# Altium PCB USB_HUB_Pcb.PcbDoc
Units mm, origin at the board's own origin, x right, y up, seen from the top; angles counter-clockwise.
Board outline 72.5 x 95.02 mm, 4 copper layers (Top Layer, Int1 (GND), Int2 (PWR), Bottom Layer), stack 1.626 mm thick; 61 components, 56 nets, 230 pads, 681 vias.
Unrouted connection lines stored in the file: 103.
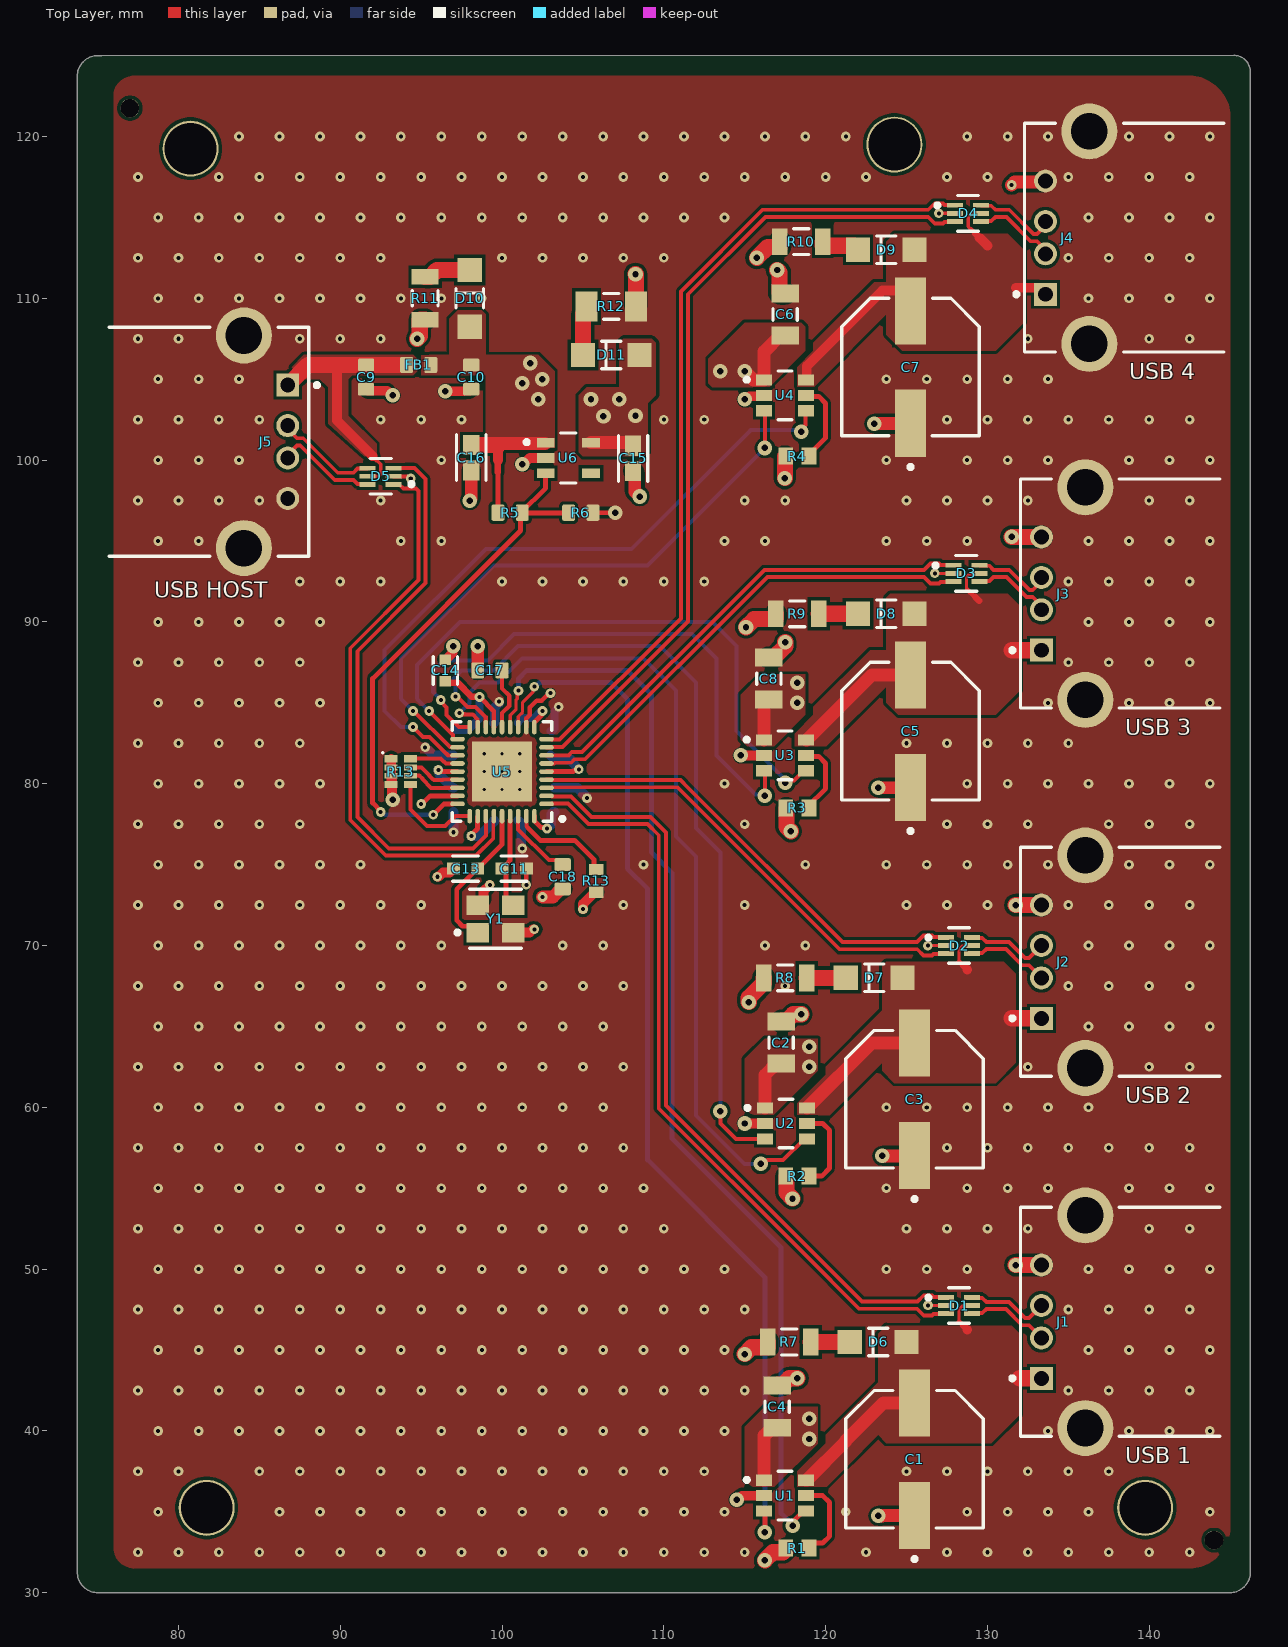
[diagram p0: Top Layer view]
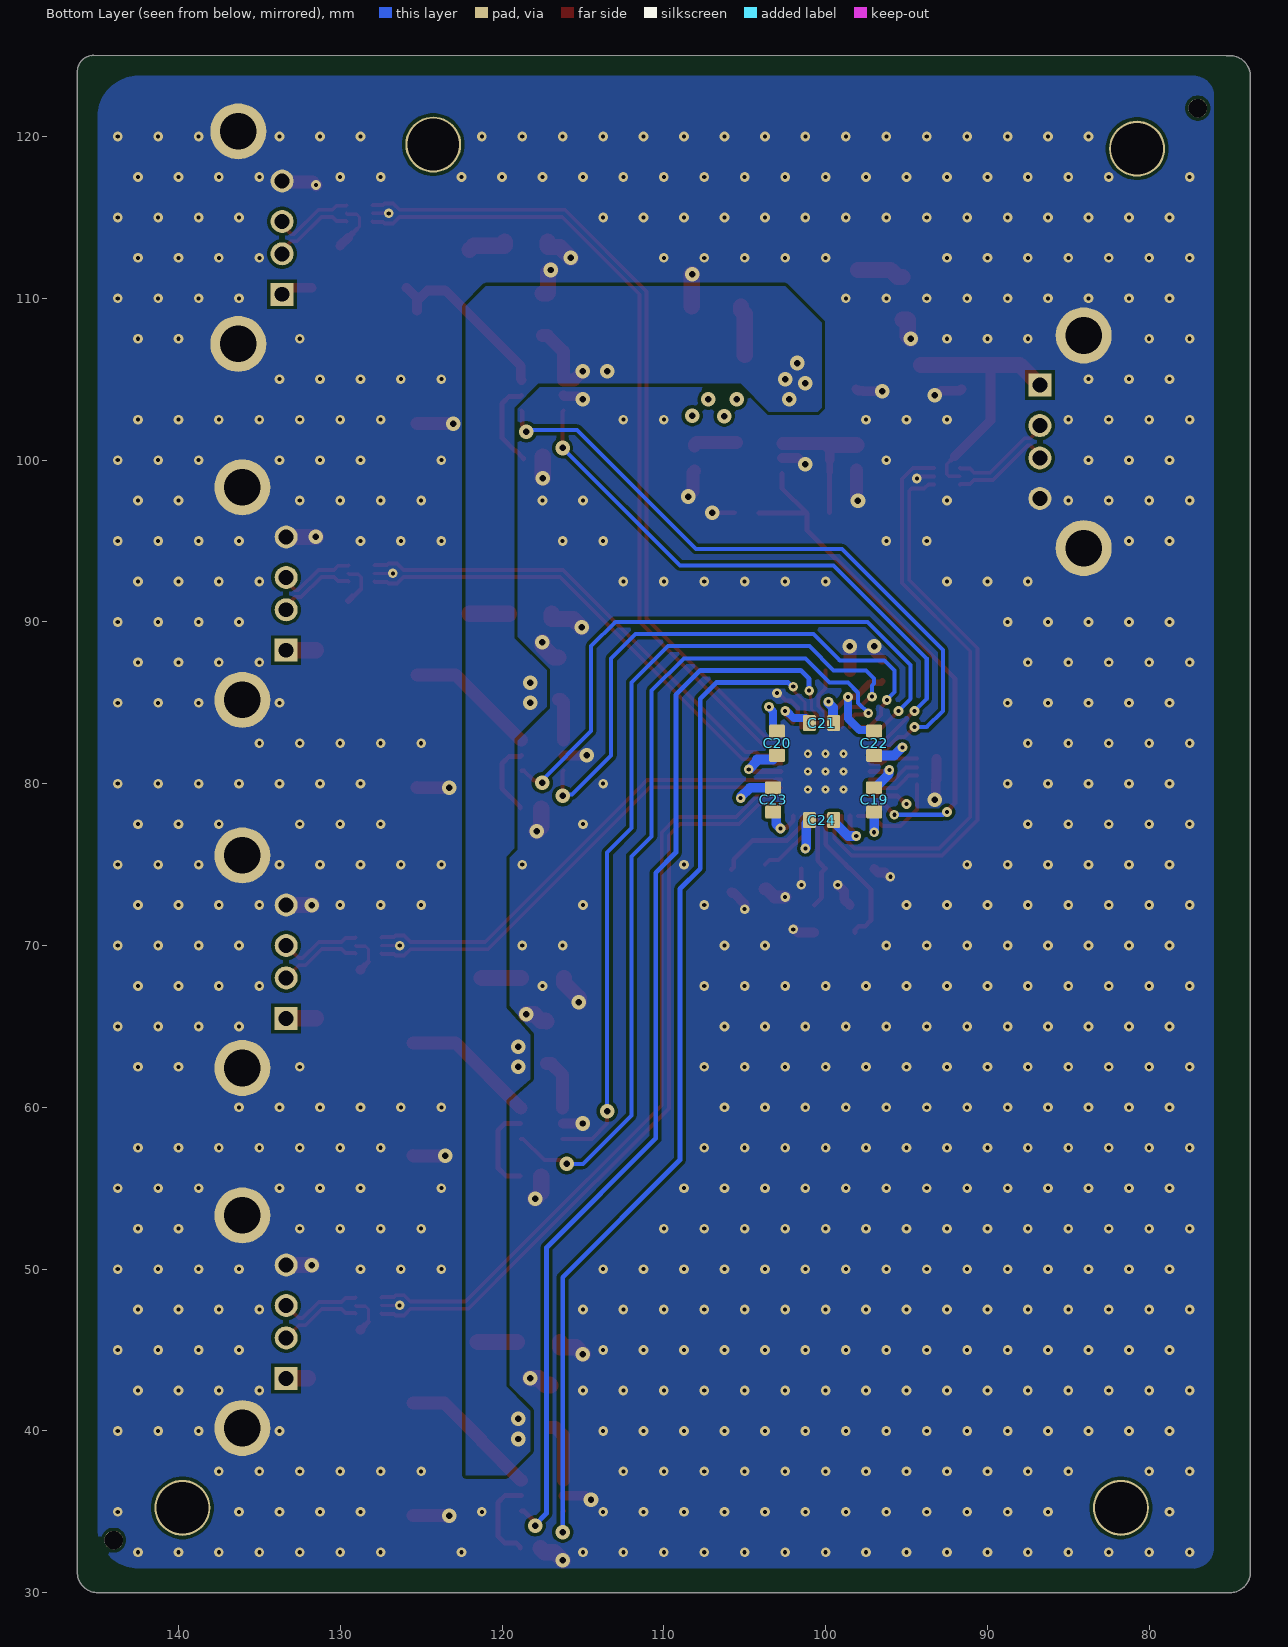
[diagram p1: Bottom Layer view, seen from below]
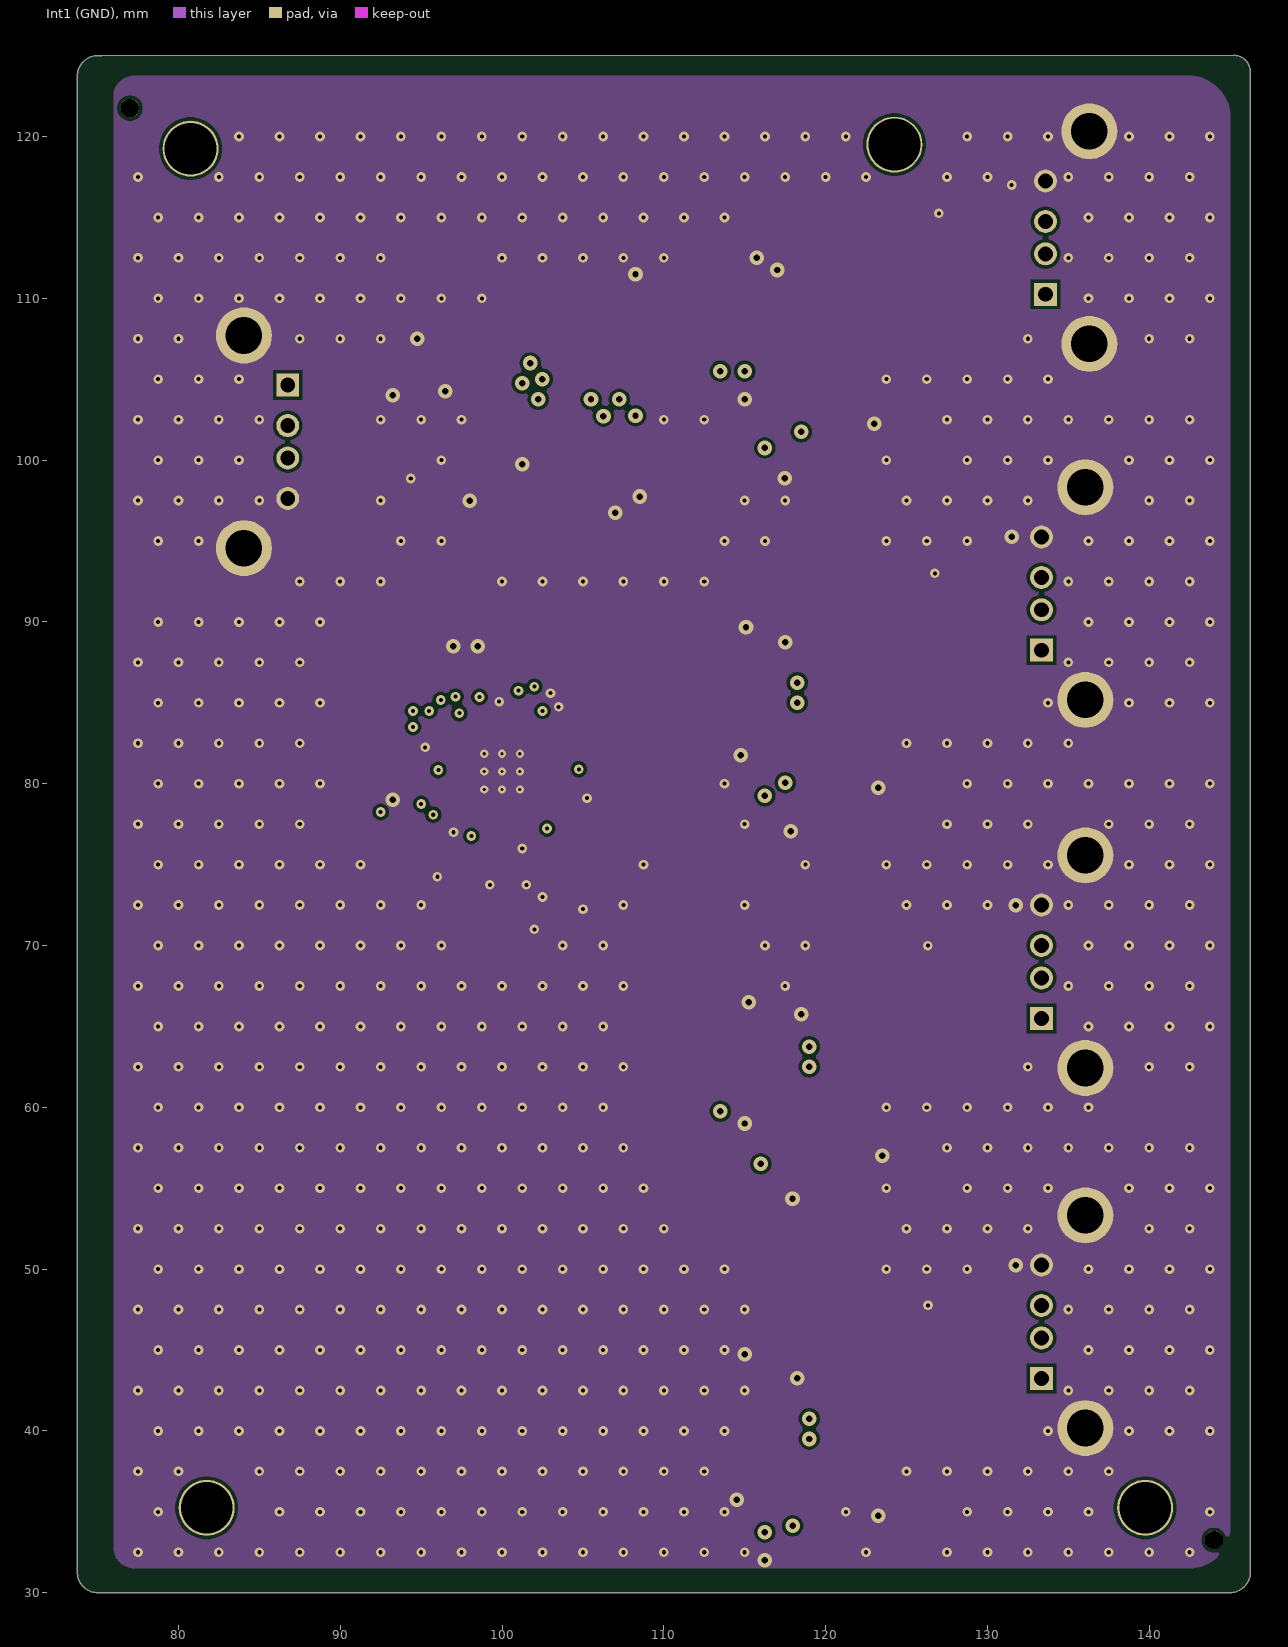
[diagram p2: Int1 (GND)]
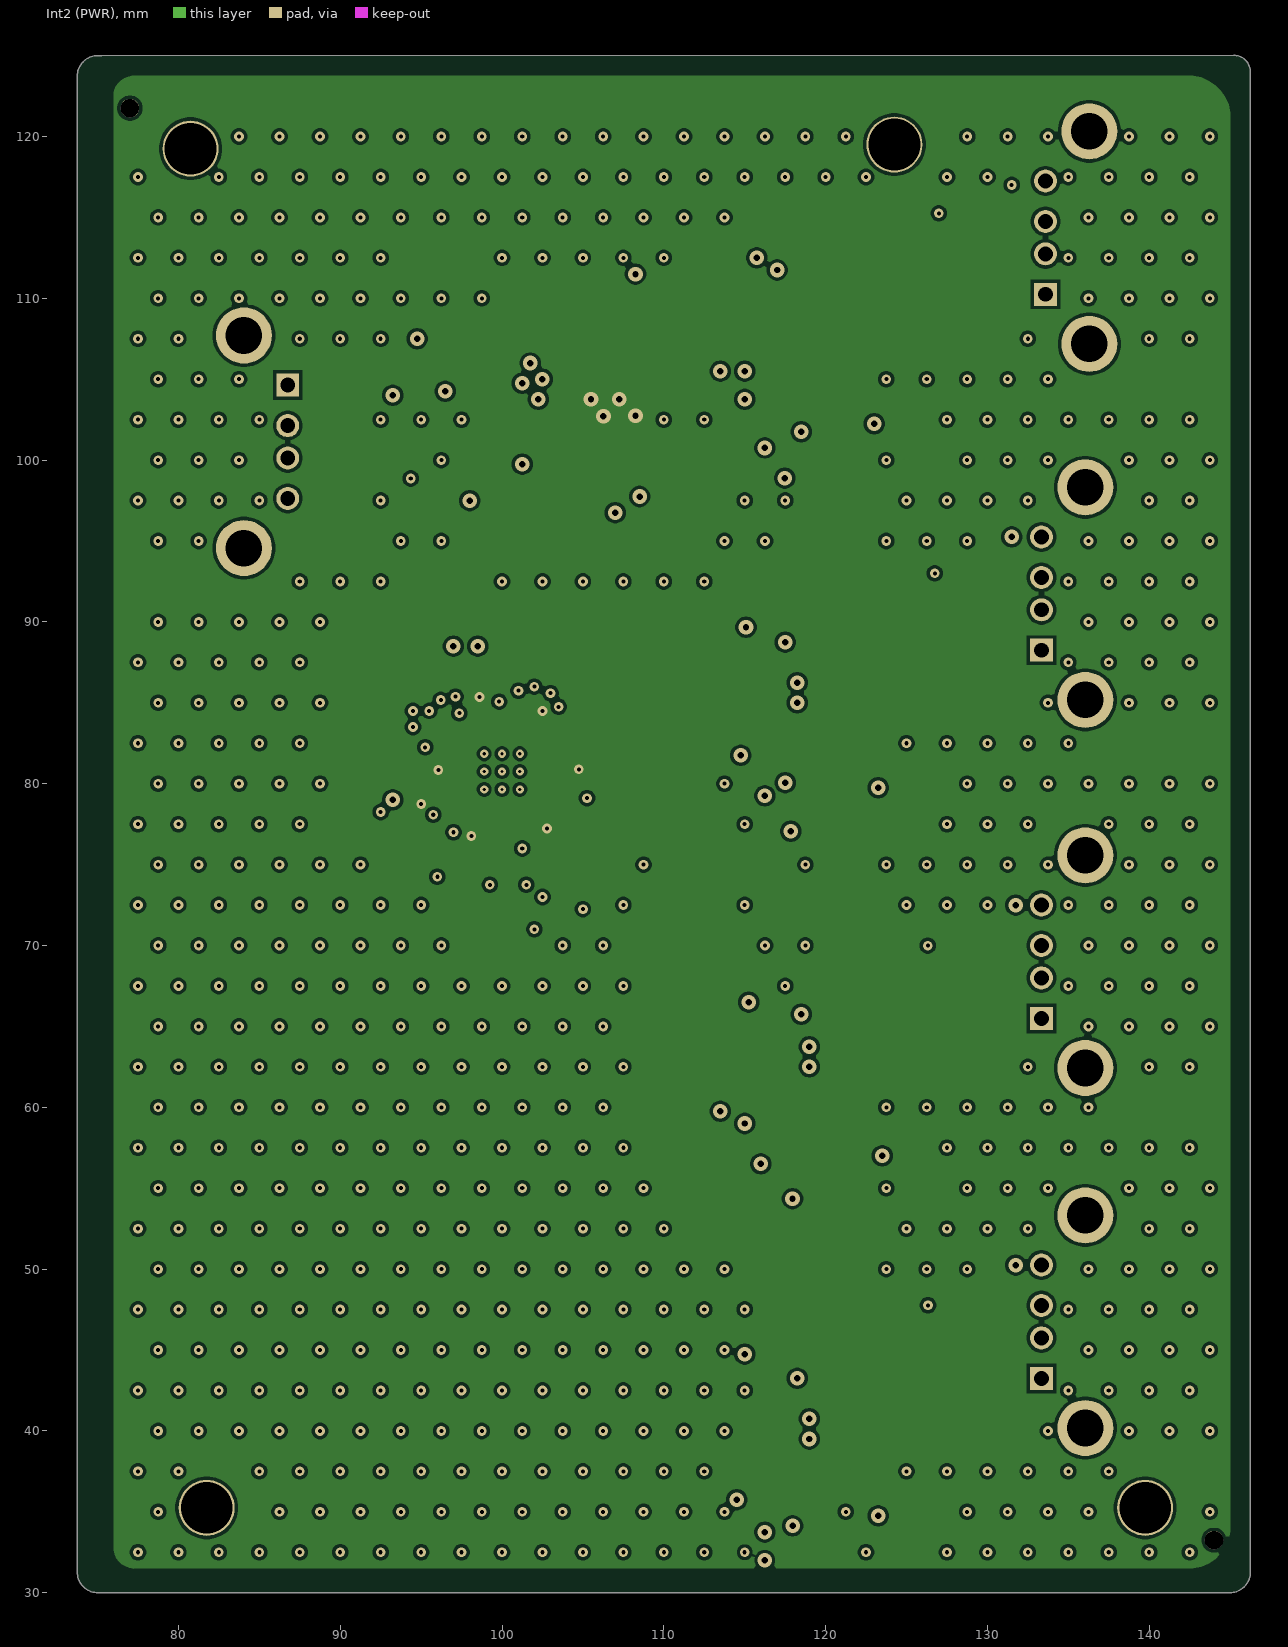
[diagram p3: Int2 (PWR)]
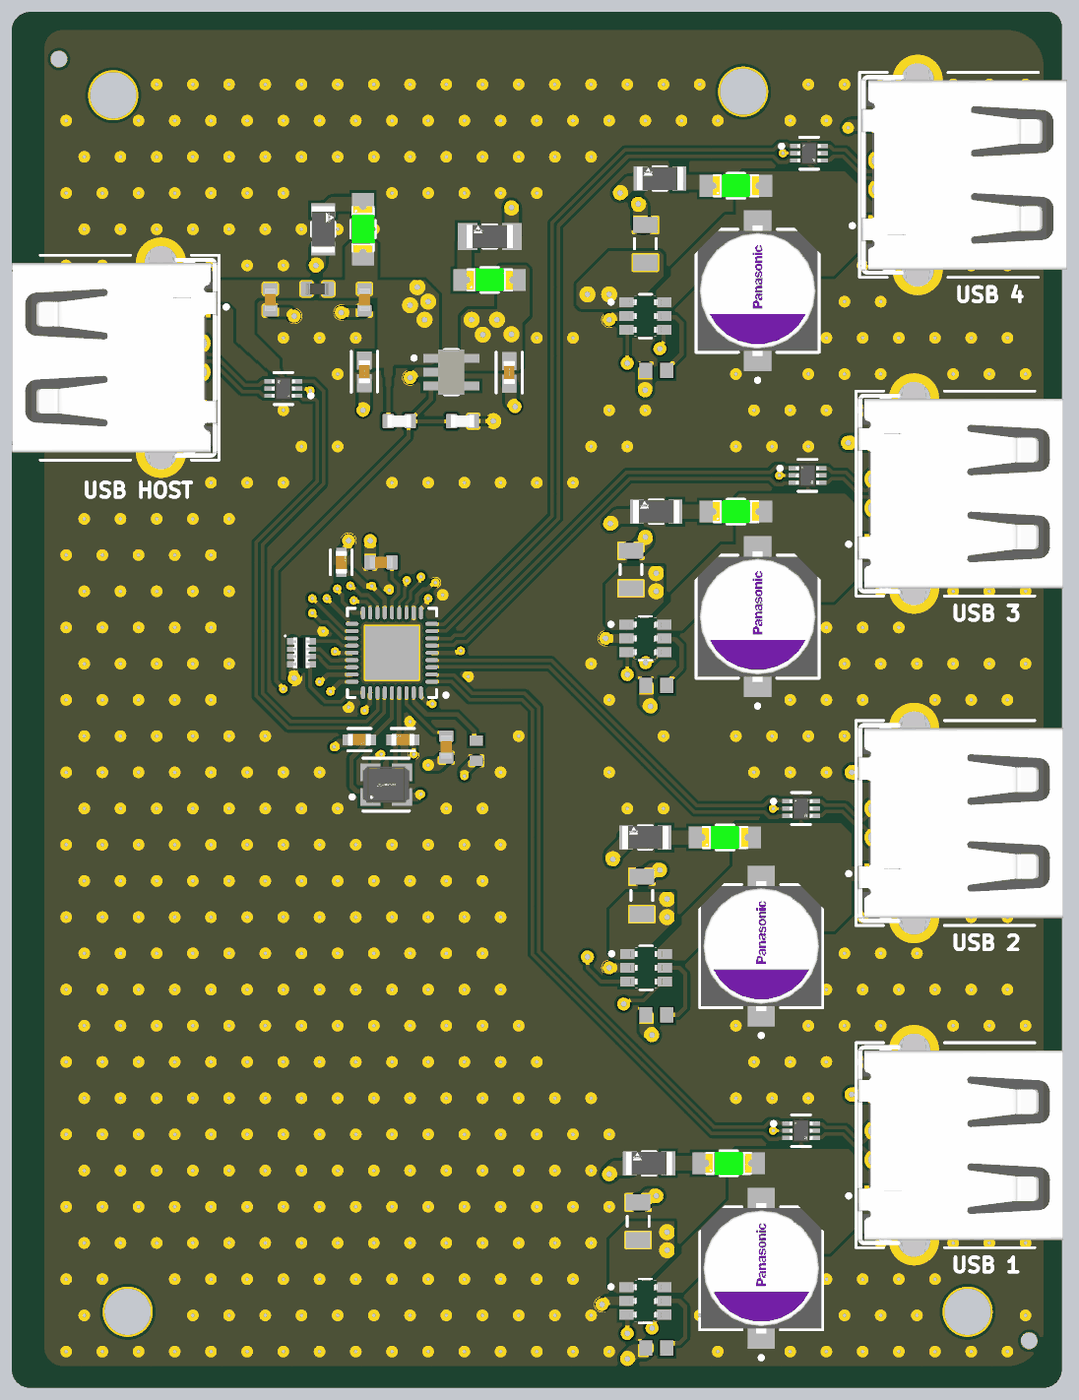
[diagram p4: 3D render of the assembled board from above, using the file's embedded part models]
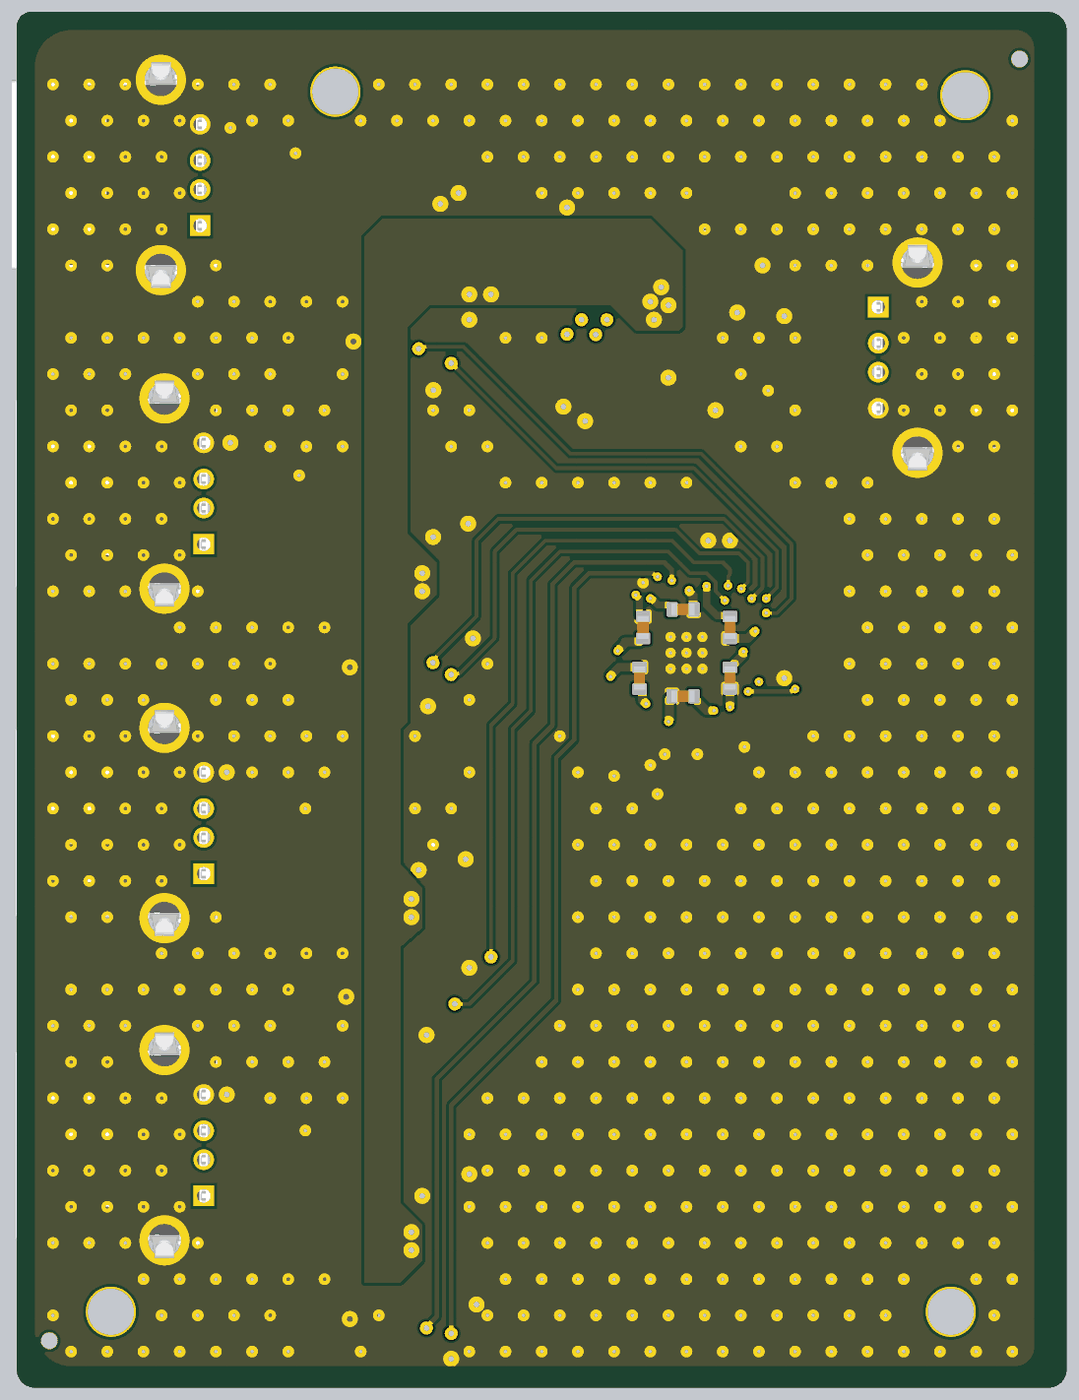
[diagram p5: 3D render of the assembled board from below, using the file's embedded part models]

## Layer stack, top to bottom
Top Solder: solder mask 0.0254, SM-001, Dk 4
Top Layer: signal copper 0.035
Dielectric 1: prepreg 0.2104, PP-017, Dk 4.74
Int1 (GND): signal copper 0.035
Dielectric 3: core 1.065, Core-039, Dk 4.6
Int2 (PWR): signal copper 0.035
Dielectric 2: prepreg 0.2104, PP-017, Dk 4.74
Bottom Layer: signal copper 0.035
Bottom Solder: solder mask 0.0254, SM-001, Dk 4

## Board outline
73.75,31.27 73.75,123.731 cw(c75.02,123.731) 75.02,125.001 75.25,125.001 145.25,125.02 145.23,125.02 cw(c145.23,124) 146.25,124 146.25,32.095 146.25,31.27 cw(c144.98,31.27) 144.98,30 144.75,30 75.5,30 75.02,30 cw(c75.02,31.27)

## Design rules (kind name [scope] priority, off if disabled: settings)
Clearance Clearance_1 [All] p1: gap=0.2 ignorepadtopadclearanceinfootprint=FALSE except(0: Hole-Hole; 0.15: SMDPad-SMDPad)
Clearance Clearance_1 [(ExistsOnLayer('Int1 (GND)') Or ExistsOnLayer('Int2 (PWR)')) vs (ExistsOnLayer('Int1 (GND)') Or ExistsOnLayer('Int2 (PWR)'))] p2: gap=0.2 ignorepadtopadclearanceinfootprint=FALSE except(0.254: Hole-Hole) sourcerule=44 cellrowname=All cellrowtype=0 cellcolname=All cellcoltype=0 innerlayers=TRUE
Clearance Clearance_2 [(ExistsOnLayer('Top Layer') Or ExistsOnLayer('Bottom Layer')) vs (ExistsOnLayer('Top Layer') Or ExistsOnLayer('Bottom Layer'))] p3: gap=0.2 ignorepadtopadclearanceinfootprint=FALSE except(0.254: Hole-Hole) sourcerule=44 cellrowname=All cellrowtype=0 cellcolname=All cellcoltype=0 outerlayers=TRUE
Clearance [All] p4: gap=0.254 ignorepadtopadclearanceinfootprint=FALSE ismatrix=TRUE
DiffPairsRouting DifferentialPairsRouting_1 [InDifferentialPairClass('All Differential Pairs')] p1: maxlimit=0.254 minlimit=0.2 mostfreqgap=0.254 toplayer_maxgap=0.2 toplayer_prefgap=0.2 toplayer_minwidth=0.242 toplayer_maxwidth=0.242 toplayer_prefwidth=0.242 bottomlayer_maxgap=0.2 bottomlayer_prefgap=0.2 bottomlayer_minwidth=0.242 bottomlayer_maxwidth=0.242 bottomlayer_prefwidth=0.242 impedanceprofiledriven=TRUE impedanceprofileid={922D21AE-9045-4F8F-8411-C6D0F4A54CC1} impedanceprofilevalue=90.000000 maxuncoupledlength=12.7
DiffPairsRouting [All] p2: maxlimit=0.254 minlimit=0.254 mostfreqgap=0.254 toplayer_minwidth=0.381 toplayer_maxwidth=0.381 toplayer_prefwidth=0.381 midlayer1_minwidth=0.381 midlayer1_maxwidth=0.381 midlayer1_prefwidth=0.381 midlayer2_minwidth=0.381 midlayer2_maxwidth=0.381 midlayer2_prefwidth=0.381 bottomlayer_minwidth=0.381 bottomlayer_maxwidth=0.381 bottomlayer_prefwidth=0.381 maxuncoupledlength=12.7
HoleSize MaxMinHoleSize_1 [All] p1: absolutevalues=TRUE maxlimit=6.2 minlimit=0.15 maxpercent=80.000 minpercent=20.000
HoleSize [All] p2: absolutevalues=TRUE maxlimit=2.54 minlimit=0.025 maxpercent=80.000 minpercent=20.000
HoleToHoleClearance [All] p1: gap=0.2 allowstackedmicrovias=TRUE
MinimumSolderMaskSliver [All] p1: minsoldermaskwidth=0.1
PlaneConnect [All] p1: planeconnectstyle=Direct reliefexpansion=0.508 reliefentries=4 reliefconductorwidth=0.254 reliefairgap=0.254
PolygonConnect [All] p1: connectstyle=Direct reliefconductorwidth=0.254 reliefentries=4 polygonreliefangle="90 Angle" airgapwidth=0.254
RoutingVias RoutingViaStyle_1 [All] p1: holewidth=0.3 width=0.7 viastyle="Through Hole" minholewidth=0.25 minwidth=0.55 maxholewidth=0.4 maxwidth=0.9
SolderMaskExpansion [All] p1: expansion=0.102 istentingtop=FALSE
SupplyNets "Schematic Supply Nets_3" [InNet('3V3')] p1: voltage=0.000
SupplyNets "Schematic Supply Nets_2" [InNet('GND')] p2: voltage=0.000
SupplyNets "Schematic Supply Nets_1" [InNet('VBUS')] p3: voltage=0.000
SupplyNets "Schematic Supply Nets" [InNet('VBUS_Filt')] p4: voltage=0.000
UnRoutedNet [All] p1: checkbadconnections=TRUE
Width MaxMinWidth_1 [All] p1: maxlimit=1 minlimit=0.2 preferedwidth=0.3 minimp=50.000000 maximp=50.000000 favimp=50.000000
Width MaxMinWidth_2 [All] p2: maxlimit=1 minlimit=0.2 preferedwidth=0.3 minimp=50.000000 maximp=50.000000 favimp=50.000000
24 further rules are at their usual default settings.

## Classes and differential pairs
differential pair "D_USB1 1 D": +"USB1 1 D_P" -"USB1 1 D_N"
differential pair "D_USB1 2 D": +"USB1 2 D_P" -"USB1 2 D_N"
differential pair "D_USB1 3 D": +"USB1 3 D_P" -"USB1 3 D_N"
differential pair "D_USB1 4 D": +"USB1 4 D_P" -"USB1 4 D_N"
differential pair "D_USB HOST1 D": +"USB HOST1 D_P" -"USB HOST1 D_N"
differential pair "D_USB 1 D": +"USB 1 D_P" -"USB 1 D_N"
differential pair "D_USB 2 D": +"USB 2 D_P" -"USB 2 D_N"
differential pair "D_USB 3 D": +"USB 3 D_P" -"USB 3 D_N"
differential pair "D_USB 4 D": +"USB 4 D_P" -"USB 4 D_N"
differential pair "D_USB HOST D": +"USB HOST D_P" -"USB HOST D_N"

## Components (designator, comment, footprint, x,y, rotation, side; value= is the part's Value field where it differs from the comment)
C1 "120u" FP-OS-CON-SMT-E7-MFG 125.5,38.25 r90 top
C2 "1u" CAPC3216X110X50LL20T25 117.25,64 r270 top
C3 "120u" FP-OS-CON-SMT-E7-MFG 125.5,60.5 r90 top
C4 "1u" CAPC3216X110X50LL20T25 117,41.5 r270 top
C5 "120u" FP-OS-CON-SMT-E7-MFG 125.25,83.25 r90 top
C6 "1u" CAPC3216X110X50LL20T25 117.5,109 r270 top
C7 "120u" FP-OS-CON-SMT-E7-MFG 125.25,105.75 r90 top
C8 "1u" CAPC3216X110X50LL20T25 116.5,86.5 r270 top
C9 "2u2" CAP_0603 91.599,105.132 r90 top
C10 "2u2" CAP_0603 98.099,105.132 r90 top
C11 "10p" FP-0603-L_1_6_0_15-W_0_81-MFG 100.75,74.75 r180 top
C13 "10p" FP-0603-L_1_6_0_15-W_0_81-MFG 97.75,74.75 r0 top
C14 "2u2" FP-GRM188-0_1-e0_2_0_5-MFG 96.5,87 r90 top
C15 "1u" FP-0603-L_1_6_0_1-W_0_8_0-IPC_A 108.099,100.105 r270 top
C16 "1u" FP-0603-L_1_6_0_1-W_0_8_0-IPC_A 98.099,100.159 r270 top
C17 "100nF" CAP_0603 99.25,87 r0 top
C18 "100nF" CAP_0603 103.75,74.25 r90 top
C19 "100n" CAP_0603 97,79 r90 bottom
C20 "100n" CAP_0603 103,82.5 r270 bottom
C21 "100n" CAP_0603 100.25,83.75 r0 bottom
C22 "100n" CAP_0603 97,82.5 r90 bottom
C23 "100n" CAP_0603 103.25,79 r270 bottom
C24 "100n" CAP_0603 100.25,77.75 r180 bottom
D1 "USBLC6-2P6" FP-SOT-666-MFG 128.25,47.75 r0 top
D2 "USBLC6-2P6" FP-SOT-666-MFG 128.25,70 r0 top
D3 "USBLC6-2P6" FP-SOT-666-MFG 128.695,93 r0 top
D4 "USBLC6-2P6" FP-SOT-666-MFG 128.805,115.25 r0 top
D5 "USBLC6-2P6" FP-SOT-666-MFG 92.5,99 r180 top
D6 "LED_GREEN" FP-HSMG-C150-MFG 123.25,45.5 r0 top
D7 "LED_GREEN" FP-HSMG-C150-MFG 123,68 r0 top
D8 "LED_GREEN" FP-HSMG-C150-MFG 123.75,90.5 r0 top
D9 "LED_GREEN" FP-HSMG-C150-MFG 123.75,113 r0 top
D10 "GREEN_LED" FP-HSMG-C150-MFG 98,110 r270 top
D11 "LED_GREEN" FP-HSMG-C150-MFG 106.75,106.5 r0 top
FB1 "120R" FB_0603 94.849,105.882 r0 top
J1 "USB1130-15-A" FP-USB1130-15-A-MFG 139.25,46.75 r90 top
J2 "USB1130-15-A" FP-USB1130-15-A-MFG 139.25,69 r90 top
J3 "USB1130-15-A" FP-USB1130-15-A-MFG 139.25,91.75 r90 top
J4 "USB1130-15-A" FP-USB1130-15-A-MFG 139.5,113.75 r90 top
J5 "USB1130-15-A" FP-USB1130-15-A-MFG 80.849,101.132 r270 top
R1 "470" RESC1608X55X30ML15T15 118.25,32.75 r0 top
R2 "470" RESC1608X55X30ML15T15 118.25,55.75 r0 top
R3 "470" RESC1608X55X30ML15T15 118.25,78.5 r0 top
R4 "470" RESC1608X55X30ML15T15 118.25,100.25 r0 top
R5 "100k" RES_0603 100.5,96.75 r180 top
R6 "100k" RES_0603 104.868,96.749 r180 top
R7 "180" FP-CRCW1206-e3-IPC_C 117.75,45.5 r180 top
R8 "180" FP-CRCW1206-e3-IPC_C 117.5,68 r180 top
R9 "180" FP-CRCW1206-e3-IPC_C 118.25,90.5 r180 top
R10 "180" FP-CRCW1206-e3-IPC_C 118.5,113.5 r180 top
R11 "180" FP-CRCW1206-e3-IPC_C 95.25,110 r90 top
R12 "82" FP-CRCW1206-e3-IPC_A 106.75,109.5 r180 top
R13 "4 resistor array" 0804 93.75,80.75 r0 top
R13 "12k" RESC1608X55X25NL10T15 105.821,73.999 r270 top
U1 "MIC2019YM6-TR" FP-SOT23-6LD-PL-1-MFG 117.5,36 r0 top
U2 "MIC2019YM6-TR" FP-SOT23-6LD-PL-1-MFG 117.545,59 r0 top
U3 "MIC2019YM6-TR" FP-SOT23-6LD-PL-1-MFG 117.5,81.75 r0 top
U4 "MIC2019YM6-TR" FP-SOT23-6LD-PL-1-MFG 117.5,104 r0 top
U5 "USB2514B-AEZC" MCHP-QFN-36_V 100,80.75 r180 top locked
U6 "MCP1755T-3302E/OT" FP-C04-091-OT-MFG 104.099,100.132 r0 top
Y1 "ABM8G-24.000MHZ-18-D2Y-T" FP-ABM8G-MFG 99.6,71.65 r0 top

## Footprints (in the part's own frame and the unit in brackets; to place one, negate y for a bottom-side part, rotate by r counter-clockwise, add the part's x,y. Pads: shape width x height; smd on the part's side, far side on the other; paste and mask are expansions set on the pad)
0804 [mm] "Chip Array, ConvexS, 8-Leads, Pitch 0.50mm,  Body 2.00x1.00mm,  IPC Medium Density"
  rect 0.8x0.45 smd mask+0: 2(0.6,0.8) 3(-0.6,0.8) 7(-0.6,-0.8) 8(0.6,-0.8)
  rect 0.8x0.35 smd mask+0: 3(-0.6,0.25) 4(0.6,0.25) 5(-0.6,-0.25) 6(0.6,-0.25)
  silkscreen extent -1.17,1.11 -1.07,1.21, body extent -0.6,-1.05 0.6,1.05, height 0.45
CAP_0603 [mm]
  rrect25% 0.8x1 smd: 1(-0.75,0) 2(0.75,0)
  body extent -0.8,-0.4 0.8,0.4, height 0.51
CAPC3216X110X50LL20T25 [mm] "Chip Capacitor, 2-Leads, Body 3.20x1.60mm, IPC High Density"
  rect 1.1x1.7 smd: 1(-1.3,0) 2(1.3,0)
  silkscreen extent -0.35,-0.75 0.35,0.75, body extent -1.7,-0.9 1.7,0.9, height 1.1
FB_0603 [mm]
  rrect25% 0.8x1 smd: 1(-0.75,0) 2(0.75,0)
  body extent -0.8,-0.4 0.8,0.4, height 0.81
FP-0603-L_1_6_0_1-W_0_8_0-IPC_A [mm]
  rect 1.258x1.012 smd paste+0 mask+0: 1(-0.777,0) 2(0.777,0)
  silkscreen extent -1.41,-0.91 1.41,0.91, body extent -1.91,-1.01 1.91,1.01, height 0.25
FP-0603-L_1_6_0_15-W_0_81-MFG [mm]
  rect 0.8x0.75 smd paste+0 mask+0: 1(-0.75,0) 2(0.75,0)
  silkscreen extent -0.8,-0.77 0.8,0.77, body extent -1.25,-0.58 1.25,0.58, height 0.25
FP-ABM8G-MFG [mm]
  rect 1.4x1.2 smd paste+0 mask+0: 1(-1.1,-0.85) 2(1.1,-0.85) 3(1.1,0.85) 4(-1.1,0.85)
  silkscreen extent -2.47,-1.82 1.6,1.82, body extent -1.9,-1.55 1.9,1.55, height 0.25
FP-C04-091-OT-MFG [mm]
  rect 1.1x0.6 smd paste+0 mask+0: 1(-1.4,0.95) 2(-1.4,0) 3(-1.4,-0.95) 4(1.4,-0.95) 5(1.4,0.95)
  silkscreen extent -2.7,-1.55 0.48,1.55, body extent -2.05,-1.9 2.05,1.9, height 0.25
FP-CRCW1206-e3-IPC_A [mm]
  rect 1.356x1.858 smd paste+0 mask+0: 1(-1.526,0) 2(1.526,0)
  silkscreen extent -0.47,-0.8 0.47,0.8, body extent -2.7,-1.43 2.7,1.43, height 0.25
FP-CRCW1206-e3-IPC_C [mm]
  rect 0.956x1.658 smd paste+0 mask+0: 1(-1.326,0) 2(1.326,0)
  silkscreen extent -0.47,-0.8 0.47,0.8, body extent -1.9,-0.97 1.9,0.97, height 0.25
FP-GRM188-0_1-e0_2_0_5-MFG [mm]
  rect 0.65x0.7 smd paste+0 mask+0: 1(-0.675,0) 2(0.675,0)
  silkscreen extent -0.85,-0.75 0.85,0.75, body extent -1.1,-0.55 1.1,0.55, height 0.25
FP-HSMG-C150-MFG [mm]
  rect 1.5x1.5 smd paste+0 mask+0: 1(-1.75,0) 2(1.75,0)
  silkscreen extent -0.6,-0.85 0.6,0.85, body extent -2.6,-0.95 2.6,0.95, height 0.25
FP-OS-CON-SMT-E7-MFG [mm]
  rect 4.15x1.9 smd paste+0 mask+0: 1(-3.475,0) 2(3.475,0)
  silkscreen extent -6.3,-4.25 4.25,4.25, body extent -5.8,-4.5 5.8,4.5, height 0.25
FP-SOT23-6LD-PL-1-MFG [mm]
  rect 0.99x0.69 smd paste+0 mask+0: 1(-1.295,0.95) 2(-1.295,0) 3(-1.295,-0.95) 4(1.295,-0.95) 5(1.295,0) 6(1.295,0.95)
  silkscreen extent -2.5,-1.5 0.42,1.5, body extent -1.89,-1.6 1.89,1.6, height 0.25
FP-SOT-666-MFG [mm]
  rect 0.99x0.3 smd paste+0 mask+0: 1(-0.805,0.5) 2(-0.805,0) 3(-0.805,-0.5) 4(0.805,-0.5) 5(0.805,0) 6(0.805,0.5)
  silkscreen extent -2.02,-1.1 0.65,1.1, body extent -1.4,-0.95 1.4,0.95, height 0.25
FP-USB1130-15-A-MFG [mm]
  rect 1.42x1.42 hole 0.92 paste-2539.97 mask+0: 1(-3.5,5.91)
  round 1.42 hole 0.92 paste-2539.97 mask+0: 2(-1,5.91) 3(1,5.91) 4(3.5,5.91)
  round 3.46 hole 2.26 paste-2539.97 mask+0: 5(-6.57,3.2) 6(6.57,3.2)
  silkscreen extent -7.07,-5.13 7.07,7.83, body extent -8.4,-7.3 8.4,7.3, height 0.25
MCHP-QFN-36_V [mm] "QFN, 36-Leads, Body 6.00x6.00mm, Pitch 0.50mm, Thermal Pad 3.70x3.70mm"
  oval 0.9x0.28 smd mask+0.05: 1(-2.75,2) 2(-2.75,1.5) 3(-2.75,1) 4(-2.75,0.5) 5(-2.75,0) 6(-2.75,-0.5) 7(-2.75,-1) 8(-2.75,-1.5) 9(-2.75,-2) 19(2.75,-2) 20(2.75,-1.5) 21(2.75,-1) 22(2.75,-0.5) 23(2.75,0) 24(2.75,0.5) 25(2.75,1) 26(2.75,1.5) 27(2.75,2)
  oval 0.28x0.9 smd mask+0.05: 10(-2,-2.75) 11(-1.5,-2.75) 12(-1,-2.75) 13(-0.5,-2.75) 14(0,-2.75) 15(0.5,-2.75) 16(1,-2.75) 17(1.5,-2.75) 18(2,-2.75) 28(2,2.75) 29(1.5,2.75) 30(1,2.75) 31(0.5,2.75) 32(0,2.75) 33(-0.5,2.75) 34(-1,2.75) 35(-1.5,2.75) 36(-2,2.75)
  rect 3.7x3.7 smd: 37(0,0)
  silkscreen extent -3.85,-3.08 3.07,3.07, body extent -3,-3 3,3, height 1
RES_0603 [mm]
  rrect25% 0.8x1 smd: 1(-0.75,0) 2(0.75,0)
  body extent -0.8,-0.43 0.8,0.43, height 0.52
RESC1608X55X25NL10T15 [mm] "Chip Resistor, 2-Leads, Body 1.70x0.90mm, IPC Medium Density"
  rect 0.7x0.9 smd: 1(-0.7,0) 2(0.7,0)
  body extent -0.85,-0.45 0.85,0.45, height 0.55
RESC1608X55X30ML15T15 [mm] "Chip Resistor, 2-Leads, Body 1.75x0.95mm, IPC Low Density"
  rect 0.9x1.05 smd: 1(-0.725,0) 2(0.725,0)
  body extent -0.87,-0.48 0.87,0.48, height 0.55

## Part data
C1 C3 C5 C7: library part CMP-05428-000021-2, "Conductive Polymer Aluminum Solid Capacitors (OS-CON) 120uF ±20% 16V RADIAL SMT 8x6.9mm", Capacitance=120uF, Case/Package=Radial, ESR (Equivalent Series Resistance)=27mR, Leakage Current=500uA, Max Operating Temperature=105°C, Min Operating Temperature=-55°C, Package Quantity=1000, Ripple Current=2.9A, Tolerance=20%, Voltage=16V
C2 C4 C6 C8: library part CMP-2000-06011-1, "Chip Capacitor, 1 uF, +/- 10%, 50 V, -55 to 125 degC, 1206 (3216 Metric), RoHS, Tape and Reel", Capacitance=1uF, Capacitance - nF=1000nF, Case Code - in=1206, Case Code - mm=3216, Case Height=1mm, Case Length=3.2mm, Case Width=1.6mm, Dielectric=X7R, Manufacturer=Kemet, Maximum Operating Temperature=+125C, Minimum Operating Temperature=-55C, Operating Temperature Range=-55Cto+125C, Package / Case=1206(3216metric), Package Description="2-Pin Surface Mount Device, Body 3.2 x 1.6 mm", Temperature Coefficient / Code=+/-15%, Tolerance=10%, Voltage Rating=50V
C9 C10: library part CAP_0603, "Capacitor SMD 0603", Supplier Part Number 1=80-C0603C225K4P
C11 C13: library part CMP-2006-03982-2, "General Purpose Ceramic Capacitor, 0603, 10pF, 5%, NP0, 30ppm/°C, 100V", Capacitance=10pF, Case Code (Imperial)=0603, Case Code (Metric)=1608, Dielectric=C0G, Dielectric Material=Ceramic, Insulation Resistance=100GR, Max Operating Temperature=125°C, Min Operating Temperature=-55°C, Package Quantity=1, Temperature Coefficient=30ppm/°C, Tolerance=5%, Voltage=100V
C14: library part CMP-2006-02836-2, "Chip Multilayer Ceramic Capacitors for General Purpose, 0603, 2.2uF, X7R, 15%, 10%, 10V", Capacitance=2.2uF, Case Code (Imperial)=0603, Case Code (Metric)=1608, Dielectric=X7R, Max Operating Temperature=125°C, Min Operating Temperature=-55°C, Package Quantity=1, Tolerance=10%, Voltage=10V
C15 C16: library part CMP-2000-07259-3, "None", Capacitance=1uF, Case Code (Imperial)=0603, Case Code (Metric)=1608, Dielectric=X7R, Max Operating Temperature=125°C, Min Operating Temperature=-55°C, Package Quantity=1, Resistor Type=Ceramic, Tolerance=10%, Voltage Rating=25V
C17 C18 C19 C20 C21 C22 C23 C24: library part CAP_0603, "Capacitor SMD 0603", Supplier Part Number 1=445-5666-1-ND
D1 D2 D3 D4 D5: library part CMP-12225-000058-1, "TVS DIODE 5.25V 17V SOT666", Breakdown Voltage=6V, Capacitance=3.5pF, Case/Package=SOT-666, Clamping Voltage=17V, Leakage Current=150nA, Max Operating Temperature=125°C, Min Operating Temperature=-40°C, Operating Supply Voltage=5V, Package Quantity=1, Peak Pulse Current=5A, Power Line Protection=Yes, Test Current=1mA
D6 D7 D8 D9 D10 D11: library part CMP-2000-05061-2, "LED GREEN DIFFUSED 1206 SMD", Colour=Green, Forward Current=20mA, Forward Voltage=2.2V, Manufacturer=Broadcom, Manufacturer Part Number=HSMG-C150, Max Junction Temp=+95°C, Power Dissipation=65mW, Reverse Voltage=5V, Temperature="-40°C to +85°C", Temperature Range High=+85°C, Temperature Range Low=-40°C
FB1: library part FB_0603, "Ferrite Bead SMD 0603", Supplier Part Number 1=81-BLM18KG121TN1D
J1 J2 J3 J4 J5: library part CMP-03329-113685452-1, "USB1130-15-A USB Connectors USB A 2.0 Skt RA High Life 15u T Hole W/Shell Stake T & R", Current Rating=3A, Max Operating Temperature=85°C, Min Operating Temperature=-40°C, Voltage Rating=30V
R1 R2 R3 R4: library part CMP-1012-00473-6, "Chip Resistor, 470 Ohm, +/- 1%, 0.1 W, -55 to 155 degC, 0603 (1608 Metric), RoHS, Tape and Reel", Manufacturer=Panasonic, Max Operating Temperature="155 degC", Min Operating Temperature="-55 degC", Package Quantity=1, Voltage Rating="75 V"
R5: library part RES_0603, "Resistor SMD 0603", Supplier Part Number 1=85Y8503
R6: library part RES_0603, "Resistor SMD 0603", Supplier Part Number 1=71-CRCW0603J-100K-E3
R7 R8 R9 R10 R11: library part CMP-2003-01848-2, "RES Thick Film, 180Ω, 1%, 0.25W, 100ppm/°C, 1206", Case Code (Imperial)=1206, Case Code (Metric)=3216, Max Operating Temperature=155°C, Min Operating Temperature=-55°C, Package Quantity=5000, Power Rating=250mW, Resistance=180R, Temperature Coefficient=100ppm/°C, Tolerance=1%, Voltage Rating=200V
R12: library part CMP-2003-02405-2, "RES Thick Film, 82Ω, 1%, 0.25W, 100ppm/°C, 1206", Case Code (Imperial)=1206, Case Code (Metric)=3216, Max Operating Temperature=155°C, Max Power Dissipation=250mW, Min Operating Temperature=-55°C, Package Quantity=10, Resistance=82R, Temperature Coefficient=100ppm/°C, Tolerance=1%, Voltage Rating=200V
R13: Supplier Part Number 1=667-EXB-28V104JX
R13: library part CMP-1659-00047-2, "Chip Resistor, 12 KOhm, +/- 1%, 100 mW, -55 to 155 degC, 0603 (1608 Metric), RoHS, Tape and Reel", Case Code (Imperial)=0603, Case Code (Metric)=1608, Max Operating Temperature="155 degC", Min Operating Temperature="-55 degC", Package Quantity=5000, Power Rating="100 mW", Resistance="12 kohm", Tolerance=1%, Voltage Rating="50 V"
U1 U2 U3 U4: library part CMP-06320-000027-1, "IC PWR SWITCH P-CHAN 1:1 SOT23-6", Case/Package=SOT-23, Max Operating Temperature=85°C, Max Output Current=2A, Max Supply Voltage=5.5V, Min Operating Temperature=-40°C, On-State Resistance=220MR, Output Voltage=6V, Package Quantity=3000
U5: library part CMP-2000-05217-1, "USB 2.0 High-Speed Hub Controller, 4 Ports, 3 to 3.6 V, 0 to 85 degC, 36-Pin QFN, RoHS, Tray", Current - Supply=70mA, Manufacturer=Microchip, Operating Temperature=-, Package / Case=36-VFQFNExposedPad, Standard Package=490, Supplier Device Package=36-QFN(6x6), Voltage - Supply=3V~3.6V
U6: library part CMP-06324-000083-1, "IC REG LINEAR 3.3V 300MA SOT23-5", Case/Package=SOT-23-5, Dropout Voltage=300mV, Max Input Voltage=16V, Max Operating Temperature=125°C, Max Output Current=300mA, Min Input Voltage=3.6V, Min Operating Temperature=-40°C, Nominal Output Voltage=3.3V, Nominal Supply Current=68uA, Output Voltage Accuracy=2%, Package Quantity=3000, Power Supply Rejection Ratio (PSRR)=80dB, Quiescent Current=100uA
Y1: library part CMP-27762-003871-2, "Crystal 24MHz ±20ppm (Tol) ±30ppm (Stability) 18pF FUND 60Ω 4-Pin SMD T/R", Case/Package=CSMD, ESR (Equivalent Series Resistance)=60R, Frequency=24MHz, Frequency Stability=30ppm, Frequency Tolerance=20ppm, Load Capacitance=18pF, Max Operating Temperature=85°C, Min Operating Temperature=-40°C, Operating Frequency="24 MHz", Package Quantity=1000

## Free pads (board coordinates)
  round 3.46 hole 3.2 paste-2539.97 mask+0: MH(80.75,119.25) MH(81.75,35.25) MH(124.25,119.5) MH(139.75,35.25)
  round 1.152 hole 1.152 paste-2539.97 mask+0: TH(77,121.75) TH(144,33.25)

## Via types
v1: diameter 0.6, hole 0.25, Top Layer to Bottom Layer, 614 vias
v2: diameter 0.9, hole 0.4, Top Layer to Bottom Layer, 58 vias
v3: diameter 0.5, hole 0.2, Top Layer to Bottom Layer, 9 vias

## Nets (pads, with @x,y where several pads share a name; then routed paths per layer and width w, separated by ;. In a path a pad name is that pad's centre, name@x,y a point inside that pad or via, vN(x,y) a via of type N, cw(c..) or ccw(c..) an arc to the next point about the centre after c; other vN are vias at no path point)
3V3: C14.1 C15.1 C19.2 C20.2 C21.2 C22.2 C23.2 C24.2 D11.2 U5.5 U5.10 U5.15 U5.23 U5.26 U5.29 U5.36 U6.5 | length 28.7
  Top Layer w0.3: v1(95,78.75) 95.061,78.75 95.561,79.25 U5.26 ; v1(96.064,80.843) 96.145,80.843 96.238,80.75 U5.23 ; 97.109,86.25 97.25,86.25 ; v1(98.107,76.766) 98.107,76.847 98.49,77.23 98.49,77.99 U5.29 ; v1(98.613,85.363) 99.49,84.486 99.49,83.51 U5.15 ; U5.36 102,77.71 102.426,77.284 102.73,77.284 v1(102.787,77.227) ; U5.10@102.01,83.8 102.443,84.233 102.443,84.443 v1(102.5,84.5) ; U5.5 104.398,80.75 104.48,80.832 104.693,80.832 v1(104.75,80.889)
  Top Layer w0.4: C14.1 96.575,86.25 97.109,86.25 ; 97.25,86.25 98.137,85.363 v1(98.613,85.363)
  Top Layer w0.8: U6.5 107.993,101.082 108.099,100.976 C15.1
  Bottom Layer w0.5: C22.2 97.076,83.326 97.9,83.326 98.613,84.039 v1(98.613,85.363) ; C21.2 101,83.8 101.25,84.05 101.969,84.05 102.419,84.5 v1(102.5,84.5)
  Bottom Layer w0.6: v1(96.064,80.843) 96.118,80.788 96.118,80.582 96.95,79.75 C19.2 ; v1(98.107,76.766) 98.616,76.766 99.5,77.65 C24.2 ; v1(102.787,77.227) 103.05,77.49 103.05,78.15 103.15,78.25 C23.2 ; C20.2 103.25,81.5 104.25,81.5 104.25,81.389 v1(104.75,80.889)
  other v2: 106.271,102.722 108.25,102.75 105.5,103.75 107.25,103.75
GND: C1.1 C2.1 C3.1 C4.1 C5.1 C6.1 C7.1 C8.1 C9.1 C10.1 C11.1 C13.1 C14.2 C15.2 C16.2 C17.1 C18.1 C19.1 C20.1 C21.1 C22.1 C23.1 C24.1 D1.2 D2.2 D3.2 D4.2 D5.2 J1.4 J1.5 J1.6 J2.4 J2.5 J2.6 J3.4 J3.5 J3.6 J4.4 J4.5 J4.6 J5.4 J5.5 J5.6 R1.1 R2.1 R3.1 R4.1 R6.1 R7.2 R8.2 R9.2 R10.2 R11.1 R12.1 R13.2@105.821,73.299 R13.3 R13.5 R13.7 U1.2 U2.2 U3.2 U4.2 U5.11 U5.37 U6.2 Y1.2 Y1.4 | length 87.8
  Top Layer w0.2: v1(126.319,69.994) 126.322,69.997 127.442,69.997 D2.2 ; v1(126.324,47.764) 126.331,47.757 127.438,47.757 D1.2 ; v1(126.75,93) D3.2 ; v1(127,115.25) D4.2
  Top Layer w0.25: D5.2 93.33,98.975 94.151,98.975 94.266,98.861 v1(94.361,98.861)
  Top Layer w0.279: v1(101.5,73.75) C11.1 ; U5.11 101.5,84.034 101.712,84.245 101.712,84.712 102.139,85.139 102.456,85.139 102.913,85.596 v1(103,85.596)
  Top Layer w0.3: R6.1 v2@106.999,96.749
  Top Layer w0.6: C9.1 91.699,104.282 92.887,104.282 93.169,104 v2(93.25,104) ; R13.3@93.15,81.55 93.15,81 R13.5 93.15,80.25 93.2,80.2 ; v2@93.2,79.05 R13.7@93.2,79.95 ; v2@93.2,79.3 v2@93.25,79.25 ; v1(96,74.25) 96.087,74.25 96.351,74.514 96.764,74.514 C13.1 ; C14.2 96.525,87.675 96.943,88.093 96.943,88.443 v2(97,88.5) ; v2(96.5,104.25) 97.667,104.25 97.699,104.282 97.999,104.282 C10.1 ; Y1.4 98.855,72.855 98.855,73.355 v1(99.25,73.75) ; Y1.2 101.713,70.8 101.913,71 v1(102,71) ; v2(101.25,99.75) 101.331,99.75 101.713,100.132 U6.2 ; v1(105,72.25) 105,72.578 105.671,73.249 105.771,73.249 R13.2@105.821,73.299 ; v2(114.5,35.75) 114.581,35.75 114.831,36 U1.2 ; v2(114.75,81.75) U3.2 ; v2(115,59) U2.2 ; v2(115,103.75) 115.081,103.75 115.286,103.955 116.16,103.955 U4.2
  Top Layer w0.8: v2(98,97.5) 98,97.527 98.099,97.626 C16.2 ; C17.1 v2(98.5,88.5) ; v1(102.5,73) 103.15,73 103.65,73.5 C18.1 ; C15.2 108.205,99.221 108.205,98.072 108.5,97.777 v2(108.5,97.75) ; v2(123,102.25) 125.225,102.25 C7.1 ; v2(123.25,34.75) 123.5,34.75 123.525,34.775 C1.1 ; v2(123.25,79.75) 125.225,79.75 C5.1 ; v2(123.5,57) 125.475,57 C3.1 ; v1(131.5,117) 131.68,117.18 133.52,117.18 J4.4
  Top Layer w1: v2(94.75,107.5) 94.921,107.671 94.921,108.652 94.943,108.674 R11.1 ; v2(108.25,111.5) 108.276,111.474 R12.1 ; v2(115,44.75) 115.421,45.171 116.402,45.171 116.424,45.193 R7.2 ; v2(115.081,89.669) 115.582,90.171 116.902,90.171 116.924,90.193 R9.2 ; v2(115.25,66.5) 115.25,66.769 116.174,67.693 R8.2 ; v2(115.75,112.5) 116.421,113.171 117.152,113.171 117.174,113.193 R10.2 ; v2(116.25,32) 116.75,32.5 117.375,32.5 R1.1@117.625,32.75 ; C8.1 116.8,87.8 117.5,88.5 v2(117.5,88.75) ; C4.1 117.05,42.85 117.35,42.85 117.75,43.25 v2(118.25,43.25) ; v2(117,111.75) 117.15,111.6 117.15,110.35 117.2,110.3 C6.1 ; C2.1 117.3,65.35 117.6,65.35 118,65.75 v2(118.5,65.75) ; v2(117.48,98.889) R4.1@117.48,100.225 ; R2.1@117.575,55.725 117.575,54.74 v2(117.954,54.36) ; R3.1@117.575,78.475 117.575,77.341 v2(117.854,77.063) ; v2(131.5,95.25) J3.4 ; v2(131.75,50.25) J1.4 ; v2(131.75,72.5) J2.4
  Bottom Layer w0.279: v1(95.25,82.25) v1@95.266,82.25
  Bottom Layer w0.5: C20.1 103.1,83.25 103.25,83.4 103.25,84.473 103.5,84.723 v1(103.5,84.75)
  Bottom Layer w0.6: v1@95.266,82.25 95.766,81.75 C22.1 ; v1(97,77) C19.1 ; C21.1 99.543,83.793 99.543,84.706 99.822,84.986 v1(99.822,85.072) ; C24.1 101.189,77.561 101.189,76.061 v1(101.25,76) ; C23.1 104.677,79.75 105.25,79.177 v1(105.25,79.111)
  other v1: 77.5,32.5 80,32.5 82.5,32.5 85,32.5 87.5,32.5 90,32.5 92.5,32.5 95,32.5 97.5,32.5 100,32.5 102.5,32.5 105,32.5 107.5,32.5 110,32.5 112.5,32.5 115,32.5 122.5,32.5 127.5,32.5 130,32.5 132.5,32.5 135,32.5 137.5,32.5 140,32.5 142.5,32.5 78.75,35 86.25,35 88.75,35 91.25,35 93.75,35 96.25,35 98.75,35 101.25,35 103.75,35 106.25,35 108.75,35 111.25,35 113.75,35 121.25,35 128.75,35 131.25,35 133.75,35 136.25,35 143.75,35 77.5,37.5 80,37.5 85,37.5 87.5,37.5 90,37.5 92.5,37.5 95,37.5 97.5,37.5 100,37.5 102.5,37.5 105,37.5 107.5,37.5 110,37.5 112.5,37.5 125,37.5 127.5,37.5 130,37.5 132.5,37.5 135,37.5 137.5,37.5 78.75,40 81.25,40 83.75,40 86.25,40 88.75,40 91.25,40 93.75,40 96.25,40 98.75,40 101.25,40 103.75,40 106.25,40 108.75,40 111.25,40 113.75,40 133.75,40 138.75,40 141.25,40 143.75,40 77.5,42.5 80,42.5 82.5,42.5 85,42.5 87.5,42.5 90,42.5 92.5,42.5 95,42.5 97.5,42.5 100,42.5 102.5,42.5 105,42.5 107.5,42.5 110,42.5 112.5,42.5 115,42.5 135,42.5 137.5,42.5 140,42.5 142.5,42.5 78.75,45 81.25,45 83.75,45 86.25,45 88.75,45 91.25,45 93.75,45 96.25,45 98.75,45 101.25,45 103.75,45 106.25,45 108.75,45 111.25,45 113.75,45 136.25,45 138.75,45 141.25,45 143.75,45 77.5,47.5 80,47.5 82.5,47.5 85,47.5 87.5,47.5 90,47.5 92.5,47.5 95,47.5 97.5,47.5 100,47.5 102.5,47.5 105,47.5 107.5,47.5 110,47.5 112.5,47.5 115,47.5 135,47.5 137.5,47.5 140,47.5 142.5,47.5 78.75,50 81.25,50 83.75,50 86.25,50 88.75,50 91.25,50 93.75,50 96.25,50 98.75,50 101.25,50 103.75,50 106.25,50 108.75,50 111.25,50 113.75,50 123.75,50 126.25,50 128.75,50 136.25,50 138.75,50 141.25,50 143.75,50 77.5,52.5 80,52.5 82.5,52.5 85,52.5 87.5,52.5 90,52.5 92.5,52.5 95,52.5 97.5,52.5 100,52.5 102.5,52.5 105,52.5 107.5,52.5 110,52.5 125,52.5 127.5,52.5 130,52.5 132.5,52.5 140,52.5 142.5,52.5 78.75,55 81.25,55 83.75,55 86.25,55 88.75,55 91.25,55 93.75,55 96.25,55 98.75,55 101.25,55 103.75,55 106.25,55 108.75,55 123.75,55 128.75,55 131.25,55 133.75,55 138.75,55 141.25,55 143.75,55 77.5,57.5 80,57.5 82.5,57.5 85,57.5 87.5,57.5 90,57.5 92.5,57.5 95,57.5 97.5,57.5 100,57.5 102.5,57.5 105,57.5 107.5,57.5 127.5,57.5 130,57.5 132.5,57.5 135,57.5 137.5,57.5 140,57.5 142.5,57.5 78.75,60 81.25,60 83.75,60 86.25,60 88.75,60 91.25,60 93.75,60 96.25,60 98.75,60 101.25,60 103.75,60 106.25,60 123.75,60 126.25,60 128.75,60 131.25,60 133.75,60 136.25,60 77.5,62.5 80,62.5 82.5,62.5 85,62.5 87.5,62.5 90,62.5 92.5,62.5 95,62.5 97.5,62.5 100,62.5 102.5,62.5 105,62.5 107.5,62.5 132.5,62.5 140,62.5 142.5,62.5 78.75,65 81.25,65 83.75,65 86.25,65 88.75,65 91.25,65 93.75,65 96.25,65 98.75,65 101.25,65 103.75,65 106.25,65 136.25,65 138.75,65 141.25,65 143.75,65 77.5,67.5 80,67.5 82.5,67.5 85,67.5 87.5,67.5 90,67.5 92.5,67.5 95,67.5 97.5,67.5 100,67.5 102.5,67.5 105,67.5 107.5,67.5 117.5,67.5 135,67.5 137.5,67.5 140,67.5 142.5,67.5 78.75,70 81.25,70 83.75,70 86.25,70 88.75,70 91.25,70 93.75,70 96.25,70 103.75,70 106.25,70 116.25,70 118.75,70 136.25,70 138.75,70 141.25,70 143.75,70 77.5,72.5 80,72.5 82.5,72.5 85,72.5 87.5,72.5 90,72.5 92.5,72.5 95,72.5 107.5,72.5 115,72.5 125,72.5 127.5,72.5 130,72.5 135,72.5 137.5,72.5 140,72.5 142.5,72.5 78.75,75 81.25,75 83.75,75 86.25,75 88.75,75 91.25,75 108.75,75 118.75,75 123.75,75 126.25,75 128.75,75 131.25,75 133.75,75 138.75,75 141.25,75 143.75,75 77.5,77.5 80,77.5 82.5,77.5 85,77.5 87.5,77.5 115,77.5 127.5,77.5 130,77.5 132.5,77.5 137.5,77.5 140,77.5 142.5,77.5 78.75,80 81.25,80 83.75,80 86.25,80 88.75,80 113.75,80 128.75,80 131.25,80 133.75,80 136.25,80 138.75,80 141.25,80 143.75,80 77.5,82.5 80,82.5 82.5,82.5 85,82.5 87.5,82.5 125,82.5 127.5,82.5 130,82.5 132.5,82.5 135,82.5 78.75,85 81.25,85 83.75,85 86.25,85 88.75,85 133.75,85 138.75,85 141.25,85 143.75,85 77.5,87.5 80,87.5 82.5,87.5 85,87.5 87.5,87.5 135,87.5 137.5,87.5 140,87.5 142.5,87.5 78.75,90 81.25,90 83.75,90 86.25,90 88.75,90 136.25,90 138.75,90 141.25,90 143.75,90 87.5,92.5 90,92.5 92.5,92.5 100,92.5 102.5,92.5 105,92.5 107.5,92.5 110,92.5 112.5,92.5 135,92.5 137.5,92.5 140,92.5 142.5,92.5 78.75,95 81.25,95 93.75,95 96.25,95 113.75,95 116.25,95 123.75,95 126.25,95 128.75,95 136.25,95 138.75,95 141.25,95 143.75,95 77.5,97.5 80,97.5 82.5,97.5 85,97.5 92.5,97.5 115,97.5 117.5,97.5 125,97.5 127.5,97.5 130,97.5 132.5,97.5 140,97.5 142.5,97.5 78.75,100 81.25,100 83.75,100 96.25,100 123.75,100 128.75,100 131.25,100 133.75,100 138.75,100 141.25,100 143.75,100 77.5,102.5 80,102.5 82.5,102.5 85,102.5 92.5,102.5 95,102.5 97.5,102.5 110,102.5 112.5,102.5 127.5,102.5 130,102.5 132.5,102.5 135,102.5 137.5,102.5 140,102.5 142.5,102.5 78.75,105 81.25,105 83.75,105 123.75,105 126.25,105 128.75,105 131.25,105 133.75,105 77.5,107.5 80,107.5 87.5,107.5 90,107.5 92.5,107.5 132.5,107.5 140,107.5 142.5,107.5 78.75,110 81.25,110 83.75,110 86.25,110 88.75,110 91.25,110 93.75,110 96.25,110 98.75,110 136.25,110 138.75,110 141.25,110 143.75,110 77.5,112.5 80,112.5 82.5,112.5 85,112.5 87.5,112.5 90,112.5 92.5,112.5 100,112.5 102.5,112.5 105,112.5 107.5,112.5 110,112.5 135,112.5 137.5,112.5 140,112.5 142.5,112.5 78.75,115 81.25,115 83.75,115 86.25,115 88.75,115 91.25,115 93.75,115 96.25,115 98.75,115 101.25,115 103.75,115 106.25,115 108.75,115 111.25,115 113.75,115 136.25,115 138.75,115 141.25,115 143.75,115 77.5,117.5 82.5,117.5 85,117.5 87.5,117.5 90,117.5 92.5,117.5 95,117.5 97.5,117.5 100,117.5 102.5,117.5 105,117.5 107.5,117.5 110,117.5 112.5,117.5 115,117.5 117.5,117.5 120,117.5 122.5,117.5 127.5,117.5 130,117.5 135,117.5 137.5,117.5 140,117.5 142.5,117.5 83.75,120 86.25,120 88.75,120 91.25,120 93.75,120 96.25,120 98.75,120 101.25,120 103.75,120 106.25,120 108.75,120 111.25,120 113.75,120 116.25,120 118.75,120 121.25,120 128.75,120 131.25,120 133.75,120 138.75,120 141.25,120 143.75,120
  other v2: 93.25,79 107,96.75
  other v3: 98.9,79.65 100,79.65 101.1,79.65 98.9,80.75 100,80.75 101.1,80.75 98.9,81.85 100,81.85 101.1,81.85
NetC11_2: C11.2 U5.33 Y1.3 | length 5.8
  Top Layer w0.3: U5.33@100.49,77.75 100.49,75.24 100.25,75 100.25,74.975 C11.2@100.025,74.75 ; Y1.3 100.25,72.95 100.25,74.525 C11.2@100.025,74.75 ; C11.2@100.025,74.75 C11.2 C11.2@100.025,74.75
NetC13_2: C13.2 U5.32 Y1.1 | length 8.8
  Top Layer w0.254: U5.32@99.995,77.995 U5.32
  Top Layer w0.3: Y1.1@98.175,70.8 98.175,70.968 97.95,71.193 97.557,71.193 97.2,71.55 97.2,73.475 98.475,74.75 C13.2@98.525,74.75 ; C13.2 C13.2@98.525,74.75 ; U5.32@99.99,77.7 99.99,77.487 99.99,76.24 98.75,75 98.75,74.975 C13.2@98.525,74.75
NetC17_2: C17.2 U5.14 | length 3.9
  Top Layer w0.25: U5.14 100,84.366 100.447,84.814 100.447,85.437 100,85.884 C17.2
NetC18_2: C18.2 U5.34 | length 4.5
  Top Layer w0.25: U5.34 101,77.175 102.9,75.275 103.475,75.275 C18.2
NetD6_1: D6.1 R7.1 | length 2.4
  Top Layer w1: R7.1 D6.1
NetD7_1: D7.1 R8.1 | length 2.4
  Top Layer w1: R8.1 D7.1
NetD8_1: D8.1 R9.1 | length 2.4
  Top Layer w1: R9.1 D8.1
NetD9_1: D9.1 R10.1 | length 2.5
  Top Layer w1: R10.1 119.826,113.272 119.848,113.25 121.75,113.25 D9.1
NetD10_1: D10.1 R11.2 | length 2.9
  Top Layer w1: R11.2 95.557,111.326 95.981,111.75 D10.1
NetD11_1: D11.1 R12.2 | length 3.1
  Top Layer w1: D11.1 105,109.025 105.224,109.249 R12.2
NetR1_2: R1.2 U1.5 | length 5.4
  Top Layer w0.3: U1.5 119.824,36 120.25,35.574 120.25,33.5 119.825,33.075 119.125,33.075 118.875,32.825 R1.2@118.875,32.75
NetR2_2: R2.2 U2.5 | length 5.5
  Top Layer w0.3: U2.5 119.824,59 120.25,58.574 120.25,56.25 119.75,55.75 R2.2@118.875,55.75
NetR3_2: R3.2 U3.5 | length 4.6
  Top Layer w0.3: U3.5 118.859,81.686 119.564,81.686 120,81.25 120,79.7 118.875,78.575 R3.2@118.875,78.5
NetR4_2: R4.2 U4.5 | length 5.5
  Top Layer w0.3: R4.2@118.675,100.05 118.675,100.125 119.125,100.575 119.2,100.575 120,101.375 120,103.5 119.564,103.936 118.859,103.936 U4.5
NetR13_1: R13.1 U5.35 | length 6.3
  Top Layer w0.2: 101.5,77.5 U5.35
  Top Layer w0.25: 101.5,77.5 101.5,77.376 101.563,77.313
  Top Layer w0.3: 101.563,77.313 102.376,76.5 104.5,76.5 105.677,75.323 105.677,74.842 R13.1
NetR13_2: R13.2@94.35,81.55 U5.22 | length 3
  Top Layer w0.25: R13.2@94.35,81.55 96.21,81.55 96.375,81.385 96.405,81.385 96.535,81.256 97.244,81.256 U5.22
NetR13_4: R13.4 U5.24 | length 3.2
  Top Layer w0.25: R13.4 95.021,81 95.525,80.496 95.525,80.475 95.75,80.25 95.773,80.25 95.805,80.218 96.323,80.218 96.355,80.25 U5.24
NetR13_6: R13.6 U5.25 | length 3.2
  Top Layer w0.25: R13.6@94.354,80.5 94.885,80.5 95.075,80.31 95.075,80.283 95.616,79.743 96.506,79.743 96.514,79.75 U5.25
NetR13_8: R13.8 U5.28 | length 5.9
  Top Layer w0.25: R13.8 94.35,78.4 95.375,77.375 96.491,77.375 97.116,78 U5.28
"USB1 1 D_N": D1.3 U5.1 | length 47.7
  Top Layer w0.242: U5.1 103.07,78.75 103.099,78.779 104.078,78.779 105.357,77.5 109,77.5 109.688,76.812 109.688,59.938 118.637,50.988 122.076,47.549 125.661,47.549 126.067,47.143 126.581,47.143 126.659,47.221 127.416,47.221 D1.3
"USB1 1 D_P": D1.1 U5.2 | length 47.7
  Top Layer w0.242: U5.2 103.07,79.25 103.099,79.221 104.261,79.221 105.54,77.942 109.183,77.942 110.129,76.996 110.129,60.121 119.25,51 122.259,47.991 125.673,47.991 126.067,48.385 126.581,48.385 126.687,48.279 127.416,48.279 D1.1
"USB1 2 D_N": D2.3 U5.3 | length 29.1
  Top Layer w0.242: U5.3 103.07,79.75 103.099,79.779 110.846,79.779 120.854,69.771 125.664,69.771 126.062,69.373 126.576,69.373 126.674,69.471 127.416,69.471 D2.3
"USB1 2 D_P": D2.1 U5.4 | length 29.1
  Top Layer w0.242: U5.4 103.07,80.25 103.099,80.221 111.029,80.221 111.5,79.75 121.037,70.213 125.659,70.213 126.062,70.615 126.576,70.615 126.662,70.529 127.416,70.529 D2.1
"USB1 3 D_N": D3.3 U5.6 | length 30.1
  Top Layer w0.242: U5.6 102.757,81.257 103.219,81.257 103.26,81.298 104.281,81.298 104.493,81.51 105.135,81.51 116.404,92.779 126.093,92.779 126.493,92.379 127.007,92.379 127.099,92.471 127.861,92.471 D3.3
"USB1 3 D_P": D3.1 U5.7 | length 30.1
  Top Layer w0.242: U5.7 102.757,81.743 103.277,81.743 103.28,81.74 104.097,81.74 104.31,81.952 104.952,81.952 116.221,93.221 126.093,93.221 126.493,93.621 127.007,93.621 127.099,93.529 127.861,93.529 D3.1
"USB1 4 D_N": D4.3 U5.8 | length 50.9
  Top Layer w0.242: U5.8 103.07,82.25 103.099,82.279 103.746,82.279 111.5,90.033 111.5,110.25 116.279,115.029 126.343,115.029 126.743,114.629 127.257,114.629 127.349,114.721 127.971,114.721 D4.3
"USB1 4 D_P": D4.1 U5.9 | length 50.9
  Top Layer w0.242: U5.9 103.07,82.75 103.099,82.721 103.563,82.721 111.058,90.216 111.058,110.433 116.096,115.471 126.343,115.471 126.743,115.871 127.257,115.871 127.349,115.779 127.971,115.779 D4.1
"USB 1 D_N": D1.4 J1.2 | length 5.1
  Top Layer w0.242: D1.4 129.084,47.279 129.683,47.279 129.933,47.529 131.143,47.529 132.143,46.529 132.561,46.529 J1.2
"USB 1 D_P": D1.6 J1.3 | length 5.1
  Top Layer w0.242: D1.6 129.084,48.221 129.683,48.221 129.933,47.971 131.326,47.971 132.326,46.971 132.561,46.971 J1.3
"USB 1 EN": U1.3 U5.12 | length 65.5
  Top Layer w0.2: U5.12 101,84.155 101.272,84.427 101.272,85.022 101.923,85.673 101.923,85.923 v1(102,86)
  Top Layer w0.3: U1.3 116.25,35.005 v2(116.25,33.75)
  Bottom Layer w0.3: v1(102,86) 102.067,86 102.317,86.25 106.75,86.25 107.75,85.25 107.75,74.75 109,73.5 109,56.75 116.25,49.5 v2(116.25,33.75)
"USB 1 OVC": U1.4 U5.13 | length 68.6
  Top Layer w0.2: U5.13 100.515,83.515 100.515,84.236 100.872,84.593 100.872,85.188 100.942,85.257 100.942,85.673 v1(101.018,85.75)
  Top Layer w0.3: v2(117.957,34.127) 118.072,34.242 118.072,34.477 118.645,35.05 U1.4
  Bottom Layer w0.3: v1(101.018,85.75) 101.018,86.482 101.536,87 107.75,87 109.25,85.5 109.25,75.75 110.5,74.5 110.5,58.08 117.25,51.33 117.25,34.905 117.957,34.198 v2(117.957,34.127)
"USB 2 D_N": D2.4 J2.2 | length 5.1
  Top Layer w0.242: D2.4 129.084,69.529 129.683,69.529 129.933,69.779 131.143,69.779 132.143,68.779 132.561,68.779 J2.2
"USB 2 D_P": D2.6 J2.3 | length 5.1
  Top Layer w0.242: D2.6 129.084,70.471 129.683,70.471 129.933,70.221 131.326,70.221 132.326,69.221 132.561,69.221 J2.3
"USB 2 EN": U2.3 U5.16 | length 52
  Top Layer w0.25: v1(97.13,85.38) 97.225,85.38 97.867,84.738 98.366,84.738 98.994,84.11 98.994,83.506 U5.16 ; v2(113.5,59.75) 113.5,59 114.45,58.05 U2.3
  Bottom Layer w0.25: v1(97.13,85.38) 97.125,85.385 97.125,86.055 97,86.18 97,86.5 97.5,87 99.5,87 101,88.5 109.75,88.5 112,86.25 112,77.25 113.5,75.75 v2(113.5,59.75)
"USB 2 OVC": U2.4 U5.17 | length 53.3
  Top Layer w0.25: v1(97.36,84.36) 97.427,84.293 97.675,84.293 97.693,84.275 98.193,84.275 98.494,83.973 98.494,83.506 U5.17 ; v2(116,56.5) 116.176,56.5 116.413,56.737 117.377,56.737 118.69,58.05 U2.4
  Bottom Layer w0.25: v1(97.36,84.36) 97.988,84.988 97.988,85.622 98.616,86.25 99.75,86.25 101.25,87.75 108.75,87.75 110.75,85.75 110.75,76.75 112,75.5 112,59.5 114.25,57.25 115,56.5 v2(116,56.5)
"USB 3 D_N": D3.4 J3.2 | length 4.9
  Top Layer w0.242: D3.4 129.529,92.529 130.128,92.529 130.378,92.779 131.169,92.779 132.419,91.529 132.802,91.529 133.34,90.991 J3.2
"USB 3 D_P": D3.6 J3.3 | length 4.9
  Top Layer w0.242: D3.6 129.529,93.471 130.128,93.471 130.378,93.221 131.352,93.221 132.602,91.971 132.802,91.971 133.34,92.509 J3.3
"USB 3 EN": U3.3 U5.18 | length 35.5
  Top Layer w0.25: v1(96.217,85.174) 96.217,85.079 96.582,84.714 96.582,84.255 97.332,83.505 97.995,83.505 U5.18 ; U3.3 116.25,80.755 v2(116.25,79.25)
  Bottom Layer w0.25: v1(96.217,85.174) 96.217,85.195 95.75,85.662 95.75,87 96.375,87.625 99.125,87.625 100.75,89.25 111.75,89.25 113.25,87.75 113.25,81.75 115.667,79.333 116.167,79.333 v2(116.25,79.25)
"USB 3 OVC": U3.4 U5.19 | length 38.5
  Top Layer w0.25: v1(95.5,84.5) 96.981,83.019 96.981,82.764 96.985,82.76 U5.19@97.24,82.76 ; v2(117.512,80.068) 117.636,80.192 118.037,80.192 118.645,80.8 U3.4
  Bottom Layer w0.25: v1(95.5,84.5) 94.75,85.25 94.75,87.346 97.404,90 113,90 114.5,88.5 114.5,83.25 117.512,80.238 v2(117.512,80.068)
"USB 4 D_N": D4.4 J4.2 | length 5.2
  Top Layer w0.242: D4.4 129.639,114.779 130.238,114.779 130.488,115.029 131.169,115.029 132.669,113.529 133.052,113.529 133.59,112.991 J4.2
"USB 4 D_P": D4.6 J4.3 | length 5.2
  Top Layer w0.242: D4.6 129.639,115.721 130.238,115.721 130.488,115.471 131.352,115.471 132.852,113.971 133.052,113.971 133.59,114.509 J4.3
"USB 4 EN": U4.3 U5.20 | length 37.4
  Top Layer w0.25: v1(94.5,84.5) 94.532,84.5 96.777,82.256 97.244,82.256 U5.20 ; U4.3 116.25,103.005 v2(116.25,100.75)
  Bottom Layer w0.25: v1(94.5,84.5) 93.75,85.25 93.75,87.75 99.5,93.5 109,93.5 v2(116.25,100.75)
"USB 4 OVC": U4.4 U5.21 | length 42.3
  Top Layer w0.25: v1(94.5,83.5) 95.125,82.875 95.521,82.875 96.561,81.835 96.592,81.835 96.671,81.756 97.244,81.756 U5.21 ; v2(118.5,101.75) 118.5,101.926 118.75,102.176 118.75,103.005 U4.4
  Bottom Layer w0.25: v1(94.5,83.5) 93.75,83.5 92.75,84.5 92.75,88.25 99,94.5 108,94.5 115.374,101.874 118.376,101.874 v2(118.5,101.75)
"USB HOST1 D_N": D5.4 J5.2 | length 6.4
  Top Layer w0.242: J5.2 86.759,101.926 87.332,101.353 87.715,101.353 89.847,99.221 90.817,99.221 91.067,99.471 91.666,99.471 D5.4
"USB HOST1 D_P": D5.6 J5.3 | length 6.4
  Top Layer w0.242: J5.3 86.759,100.338 87.332,100.911 87.532,100.911 89.664,98.779 90.817,98.779 91.067,98.529 91.666,98.529 D5.6
"USB HOST D_N": D5.3 U5.30 | length 35.2
  Top Layer w0.242: D5.3 94.599,99.5 95.273,98.827 95.273,92.398 91.062,88.188 91.062,77.938 93,76 98.22,76 99.019,76.799 99.019,77.496 99.007,77.507 99.007,77.993 U5.30
"USB HOST D_P": D5.1 U5.31 | length 35.4
  Top Layer w0.242: D5.1 93.65,98.5 93.91,98.24 94.689,98.24 94.831,98.098 94.831,92.581 90.621,88.371 90.621,77.754 92.817,75.558 98.403,75.558 99.461,76.616 99.461,77.641 99.5,77.68 U5.31
VBUS: C9.2 D5.5 FB1.1 J5.1 | length 16.6
  Top Layer w0.2: D5.5 92.393,99 92.51,99.117 92.51,99.754 92.264,100 92.25,100
  Top Layer w0.3: 92,100.25 92.25,100
  Top Layer w0.6: 89.804,105.882 89.804,102.446 92,100.25
  Top Layer w1: J5.1 88.009,105.882 89.804,105.882 C9.2 FB1.1
"VBUS 1": C1.2 D1.5 D6.2 J1.1 U1.6 | length 12.4
  Top Layer w0.2: 128.25,46.75 128.25,47.514 128.436,47.7 129.005,47.7 D1.5
  Top Layer w0.3: 128.25,46.75 128.5,46.5
  Top Layer w0.4: 128.5,46.5 128.75,46.25
  Top Layer w0.8: U1.6 118.835,36.95 121.23,39.345 121.23,39.385 123.57,41.725 C1.2
  Top Layer w1: 132,43.25 J1.1
"VBUS 2": C3.2 D2.5 D7.2 J2.1 U2.6 | length 12.5
  Top Layer w0.2: 128.25,69 128.25,69.764 128.436,69.95 129.005,69.95 D2.5
  Top Layer w0.3: 128.25,69 128.5,68.75
  Top Layer w0.4: 128.5,68.75 128.75,68.5
  Top Layer w0.8: U2.6 122.865,63.975 C3.2
  Top Layer w1: 131.5,65.5 J2.1
"VBUS 3": C5.2 D3.5 D8.2 J3.1 U3.6 | length 12.7
  Top Layer w0.2: 128.75,92 128.705,92.045 128.705,92.774 128.881,92.95 129.45,92.95 D3.5
  Top Layer w0.3: 128.75,92 129.205,91.545 129.25,91.545
  Top Layer w0.4: 129.25,91.545 129.5,91.295
  Top Layer w0.8: U3.6 118.835,82.7 122.86,86.725 C5.2
  Top Layer w1: 131.5,88.25 J3.1
"VBUS 4": C7.2 D4.5 D9.2 J4.1 U4.6 | length 16.4
  Top Layer w0.2: 129,114.25 128.815,114.435 128.815,115.024 128.991,115.2 129.56,115.2 D4.5
  Top Layer w0.3: 129,114.25 129.25,114
  Top Layer w0.4: 129.25,114 129.5,113.75
  Top Layer w0.6: U4.6 U4.6 118.841,104.995 118.841,105.816 123.501,110.476 124.6,110.476 C7.2@125.25,109.826 ; C7.2 C7.2@125.25,109.826 ; C7.2@125.9,110.66 125.25,110.01 C7.2@125.25,109.826 ; 129.5,113.75 130,113.25 ; 131.75,110.66 133.18,110.66 J4.1
VBUS_DET: R5.1 R6.2 U5.27 U6.3 | length 33.3
  Top Layer w0.3: v1(92.5,78.25) 92.5,78.311 92,78.811 92,86.5 101.147,95.647 101.147,96.72 R5.1@101.162,96.734 ; v1(95.75,78.081) 96.419,78.75 U5.27@96.95,78.75 ; U6.3 102.699,98.271 R5.1@101.162,96.734 ; R6.2@104.118,96.734 R5.1@101.162,96.734
  Bottom Layer w0.3: v1(92.5,78.25) 92.581,78.25 92.75,78.081 v1(95.75,78.081)
VBUS_Filt: C2.2 C4.2 C6.2 C8.2 C10.2 C16.1 D10.2 FB1.2 R5.2 U1.1 U2.1 U3.1 U4.1 U6.1 | length 23.4
  Top Layer w0.3: R5.2 99.75,99.25
  Top Layer w0.4: 99.75,99.25 99.75,100
  Top Layer w0.6: 99.75,100 99.75,100.75
  Top Layer w0.8: 99.686,100.936 99.75,101 ; 99.75,100.75 99.75,101 ; U6.1@102.649,101.032 99.782,101.032 99.75,101 ; v2(115,105.5) 115.55,104.95 U4.1@116.11,104.95 ; U1.1 116.205,39.705 116.7,40.2 C4.2 ; U3.1 116.205,85.05 116.355,85.2 C8.2 ; U4.1 116.205,106.705 117.2,107.7 C6.2 ; U2.1 116.25,62 116.95,62.7 C2.2
  Top Layer w1: C16.1 99.686,100.936
  other v2: 119,39.5 119,40.75 119,62.5 119,63.75 118.25,85 118.25,86.25 102.25,103.75 101.25,104.75 102.5,105 113.5,105.5 101.75,106
pads on no net: U6.4

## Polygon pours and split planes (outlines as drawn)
GND on Top Layer "GND_L01_P030" (solid, remove dead copper, pour order 30): 76,122.5 76,122.25 76,32.75 ccw(c77.302,32.802) 77.355,31.5 142.46,31.5 ccw(c142.46,34.04) 145,34.04 145,121.21 ccw(c142.46,121.21) 142.46,123.75 77.25,123.75 ccw(c77.25,122.5)
"VBUS 1" on Top Layer "VBUS_1_L01_P029" (solid, pour order 29): 124.5,43 123.25,43 120,39.75 120,39.25 118.25,37.5 118.25,36.563 120.063,36.563 124.5,41 124.5,42.25
"VBUS 2" on Top Layer "VBUS_2_L01_P028" (solid, pour order 28): 124.75,66 123.5,66 120,62.5 120,62 118.25,60.25 118.25,59.5 120.25,59.5 124.75,64 124.75,65.25
"VBUS 3" on Top Layer "VBUS_3_L01_P027" (solid, pour order 27): 124,88.25 122.75,88.25 119.25,84.75 119.25,84.25 118.08,83.08 118.08,82.301 120.051,82.301 124,86.25 124,87.5
"VBUS 4" on Top Layer "VBUS_4_L01_P025" (solid, pour order 25): 124,111 123,111 121,109 119.25,107.25 119.25,106.75 118.25,105.75 118.25,104.5 119.25,104.5 124,109.25 124,109.5
VBUS on Top Layer "VBUS_L01_P024" (solid, pour order 24): 87,105.75 87.75,105 88.75,105 89.25,104.5 89.25,102.25 91.5,100.25 92.25,100.25 92.25,101 90.5,102.75 90.5,105 90.75,105.25 94.5,105.25 94.75,105.5 94.75,106.25 94.5,106.5 87.75,106.5
3V3 on Top Layer "3V3_L01_P023" (solid, pour order 23): 107.25,104.25 107.25,107.25 107.5,107.5 109.25,107.5 109.5,107.25 109.5,104 109,103.5 108,103.5
VBUS_Filt on Top Layer "VBUS_FILT_L01_P022" (solid, pour order 22): 99,105.75 99,109 98.75,109.25 97.25,109.25 96.75,108.75 96.75,105.75
"VBUS 4" on Top Layer "VBUS_4_L01_P021" (solid, pour order 21): 132.25,108.5 130.5,106.75 124.75,106.75 123.75,107.75 123.75,113.5 124.25,114 131.25,114 132.25,113
"VBUS 3" on Top Layer "VBUS_3_L01_P019" (solid, pour order 19): 132,85.75 130.5,84.25 124.5,84.25 123.75,85 123.75,91.5 124,91.75 131.25,91.75 132,91
"VBUS 2" on Top Layer "VBUS_2_L01_P018" (solid, pour order 18): 131.75,62.75 130.5,61.5 124.25,61.5 123.5,62.25 123.5,68.75 123.75,69 131,69 131.75,68.25
"VBUS 1" on Top Layer "VBUS_1_L01_P017" (solid, pour order 17): 132,41 130.25,39.25 123.75,39.25 123.25,39.75 123.25,46 123.75,46.5 123.759,46.491 130.491,46.491 130.5,46.5 131.5,46.5 132,46
VBUS_Filt on Top Layer "VBUS_FILT_L01_P016" (solid, pour order 16): 119.5,41.5 119.5,39.218 116.782,36.5 115.5,36.5 115,37 115,40.25 116.25,41.5
VBUS_Filt on Top Layer "VBUS_FILT_L01_P013" (solid, pour order 13): 119.5,64.25 119.5,62.25 119,61.75 116.75,59.5 115.5,59.5 115,60 115,63 116.25,64.25
VBUS_Filt on Top Layer "VBUS_FILT_L01_P011" (solid, pour order 11): 112.75,106.25 115,108.5 118.5,108.5 118.75,108.25 118.75,106.75 116.5,104.5 113,104.5 112.75,104.75
VBUS_Filt on Top Layer "VBUS_FILT_L01_P010" (solid, pour order 10): 118.75,86.75 118.75,84.25 116.813,82.313 115.168,82.313 114.75,82.731 114.75,85.5 116,86.75
3V3 on Top Layer "3V3_L01_P005" (solid, pour order 5): 105,100.25 104.75,100.5 104.75,104 105.25,104.5 108.5,104.5 109,104 109,100.5 108.75,100.25
VBUS_Filt on Top Layer "VBUS_FILT_L01_P004" (solid, pour order 4): 102.25,106.5 103.25,105.5 103.25,100.75 99.5,100.75 99,101.25 99,105.25 98.75,105.25 95,105.25 95,106.496 95.504,106.504 95.5,106.5
GND on Bottom Layer "GND_L04_P031" (solid, pour order 31): 76,122.5 76,122.25 76,32.75 ccw(c77.302,32.802) 77.355,31.5 142.46,31.5 ccw(c142.46,34.04) 145,34.04 145,121.21 ccw(c142.46,121.21) 142.46,123.75 77.25,123.75 ccw(c77.25,122.5)
VBUS_Filt on Bottom Layer "VBUS_FILT_L04_P015" (solid, pour order 15): 120,43 118.25,41.25 118.25,38.75 119.75,37.25 120,37.25 120.25,37.5 120.25,43
VBUS_Filt on Bottom Layer "VBUS_FILT_L04_P012" (solid, pour order 12): 120.25,66.75 118.25,64.5 118.25,61.75 120.25,60
VBUS_Filt on Bottom Layer "VBUS_FILT_L04_P008" (solid, pour order 8): 117.75,84.25 117.25,84.75 117.25,87 119.25,89 120,89 120.25,88.75 120.25,81.75
VBUS_Filt on Bottom Layer "VBUS_FILT_L04_P007" (solid, pour order 7): 118,106.5 118,104.75 115.25,104.75 113,104.75 112.75,105 111,106.75
VBUS_Filt on Bottom Layer "VBUS_FILT_L04_P006" (solid, pour order 6): 100.5,103 100.25,103.25 100.25,108.5 102.5,110.75 121,110.75 122.25,109.5 122.25,37.25 119.75,37.25 119.75,75.5 119.25,76 119.25,103.25 117.75,104.75 105.25,104.75 103.5,103 101.75,103
GND on Int1 (GND) "GND_L02_P000" (solid, pour order 0): 76,122.5 76,122.25 76,32.75 ccw(c77.302,32.802) 77.355,31.5 142.46,31.5 ccw(c142.46,34.04) 145,34.04 145,121.21 ccw(c142.46,121.21) 142.46,123.75 77.25,123.75 ccw(c77.25,122.5)
3V3 on Int2 (PWR) "3V3_L03_P032" (solid, pour order 32): 76,122.5 76,122.25 76,32.75 ccw(c77.302,32.802) 77.355,31.5 142.46,31.5 ccw(c142.46,34.04) 145,34.04 145,121.21 ccw(c142.46,121.21) 142.46,123.75 77.25,123.75 ccw(c77.25,122.5)

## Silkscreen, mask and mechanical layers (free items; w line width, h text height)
Top Overlay:
  text "USB 4" at 138.754,105.004 h1
  text "USB HOST" at 78.504,91.504 h1
  text "USB 3" at 138.504,83.004 h1
  text "USB 2" at 138.504,60.254 h1
  text "USB 1" at 138.504,38.004 h1
Mechanical 1:
  the board outline again, w0.254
